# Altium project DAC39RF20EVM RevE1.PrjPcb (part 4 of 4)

## Sheet DUT Power.SchDoc: DAC39RF20 Power Connections
size 431 x 279 mm; Date: Not shown in title block; ApprovedBy: Not shown in title block; CheckedBy: Not shown in title block; Author: Not shown in title block; CompanyName: Not shown in title block; Engineer: Not shown in title block; Organization: Not shown in title block; Address1: Not shown in title block; Address2: Not shown in title block; Address3: Not shown in title block; Address4: Not shown in title block; DocumentNumber: 1; Revision: Use project parameter SCH_Rev; SheetNumber: 16; SheetTotal: 21; PageSetup: Record=PageOptions¦CenterHorizontal=True¦CenterVertical=True¦PrintScale=1.00¦XCorrection=1.00¦YCorrection=1.00¦PrintKind=0¦BorderSize=5000000¦LeftOffset=0¦BottomOffset=0¦Orientation=2¦PaperLength=1000¦PaperWidth=1000¦Scale=100¦PaperSource=15¦PrintQuality=600¦MediaType=1¦DitherType=10¦PaperKind=Letter¦PrintScaleMode=1
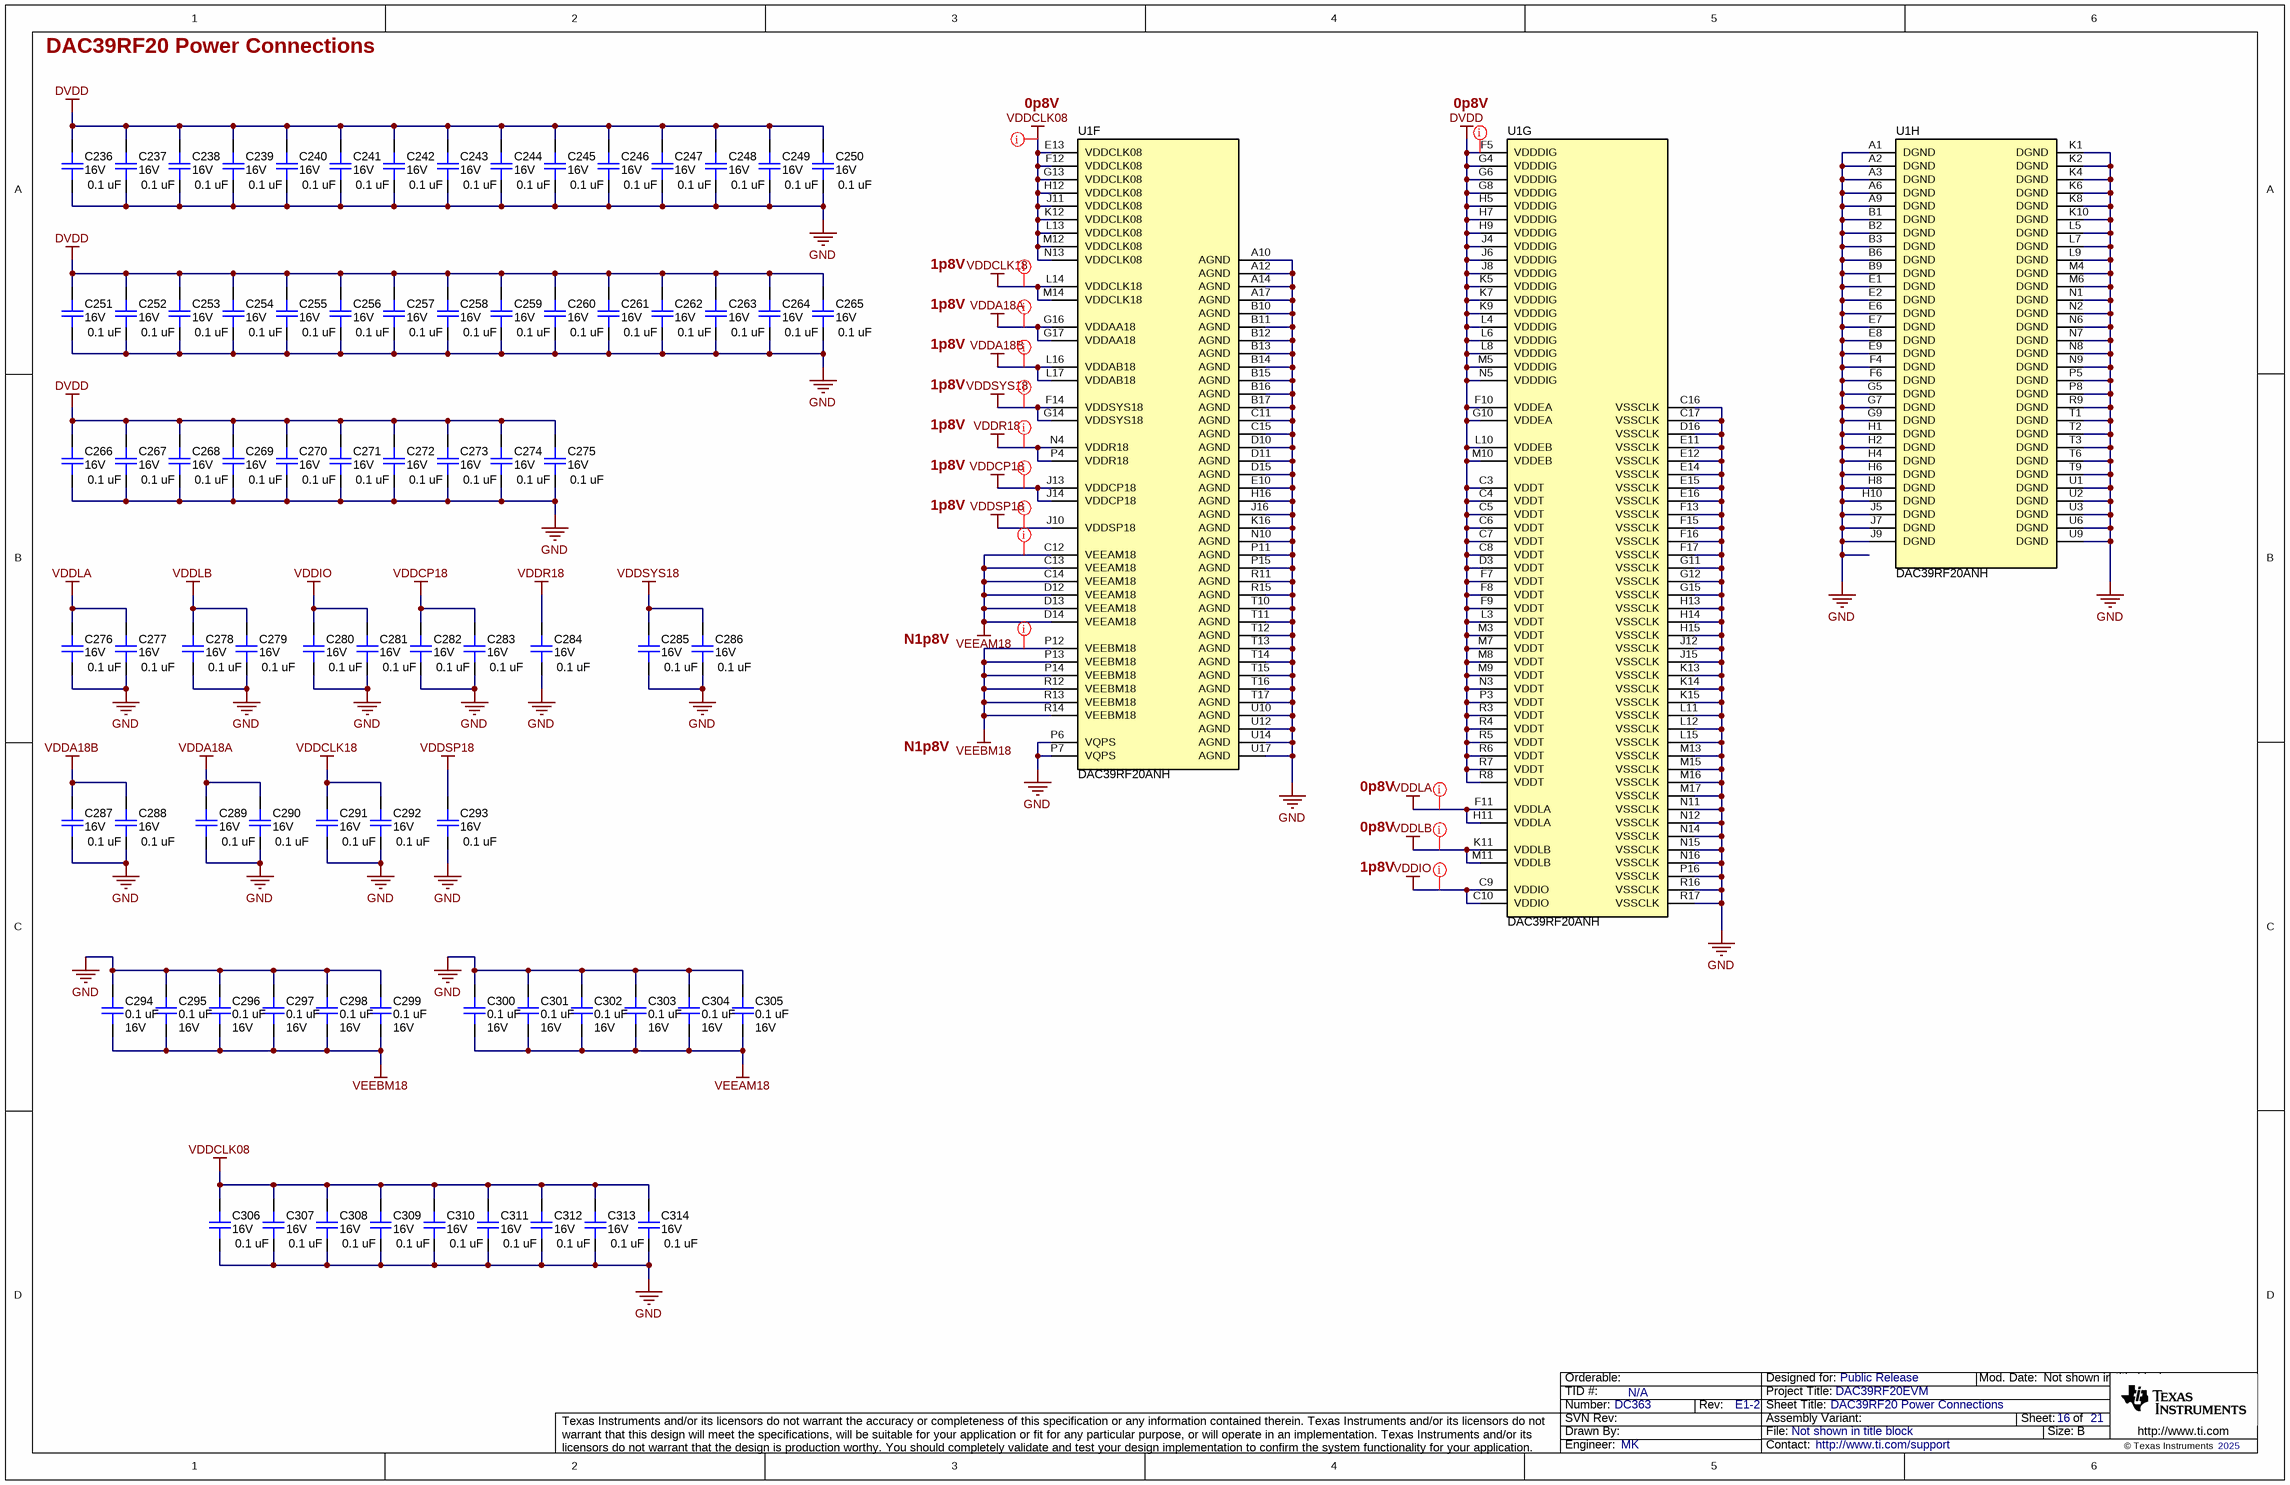
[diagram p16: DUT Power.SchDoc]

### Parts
C236  value 0.1 uF  Voltage - Rated: 16V  [0201_cap]  (hidden comment: GRM033Z71C104KE14D)
C237  value 0.1 uF  Voltage - Rated: 16V  [0201_cap]  (hidden comment: GRM033Z71C104KE14D)
C238  value 0.1 uF  Voltage - Rated: 16V  [0201_cap]  (hidden comment: GRM033Z71C104KE14D)
C239  value 0.1 uF  Voltage - Rated: 16V  [0201_cap]  (hidden comment: GRM033Z71C104KE14D)
C240  value 0.1 uF  Voltage - Rated: 16V  [0201_cap]  (hidden comment: GRM033Z71C104KE14D)
C241  value 0.1 uF  Voltage - Rated: 16V  [0201_cap]  (hidden comment: GRM033Z71C104KE14D)
C242  value 0.1 uF  Voltage - Rated: 16V  [0201_cap]  (hidden comment: GRM033Z71C104KE14D)
C243  value 0.1 uF  Voltage - Rated: 16V  [0201_cap]  (hidden comment: GRM033Z71C104KE14D)
C244  value 0.1 uF  Voltage - Rated: 16V  [0201_cap]  (hidden comment: GRM033Z71C104KE14D)
C245  value 0.1 uF  Voltage - Rated: 16V  [0201_cap]  (hidden comment: GRM033Z71C104KE14D)
C246  value 0.1 uF  Voltage - Rated: 16V  [0201_cap]  (hidden comment: GRM033Z71C104KE14D)
C247  value 0.1 uF  Voltage - Rated: 16V  [0201_cap]  (hidden comment: GRM033Z71C104KE14D)
C248  value 0.1 uF  Voltage - Rated: 16V  [0201_cap]  (hidden comment: GRM033Z71C104KE14D)
C249  value 0.1 uF  Voltage - Rated: 16V  [0201_cap]  (hidden comment: GRM033Z71C104KE14D)
C250  value 0.1 uF  Voltage - Rated: 16V  [0201_cap]  (hidden comment: GRM033Z71C104KE14D)
C251  value 0.1 uF  Voltage - Rated: 16V  [0201_cap]  (hidden comment: GRM033Z71C104KE14D)
C252  value 0.1 uF  Voltage - Rated: 16V  [0201_cap]  (hidden comment: GRM033Z71C104KE14D)
C253  value 0.1 uF  Voltage - Rated: 16V  [0201_cap]  (hidden comment: GRM033Z71C104KE14D)
C254  value 0.1 uF  Voltage - Rated: 16V  [0201_cap]  (hidden comment: GRM033Z71C104KE14D)
C255  value 0.1 uF  Voltage - Rated: 16V  [0201_cap]  (hidden comment: GRM033Z71C104KE14D)
C256  value 0.1 uF  Voltage - Rated: 16V  [0201_cap]  (hidden comment: GRM033Z71C104KE14D)
C257  value 0.1 uF  Voltage - Rated: 16V  [0201_cap]  (hidden comment: GRM033Z71C104KE14D)
C258  value 0.1 uF  Voltage - Rated: 16V  [0201_cap]  (hidden comment: GRM033Z71C104KE14D)
C259  value 0.1 uF  Voltage - Rated: 16V  [0201_cap]  (hidden comment: GRM033Z71C104KE14D)
C260  value 0.1 uF  Voltage - Rated: 16V  [0201_cap]  (hidden comment: GRM033Z71C104KE14D)
C261  value 0.1 uF  Voltage - Rated: 16V  [0201_cap]  (hidden comment: GRM033Z71C104KE14D)
C262  value 0.1 uF  Voltage - Rated: 16V  [0201_cap]  (hidden comment: GRM033Z71C104KE14D)
C263  value 0.1 uF  Voltage - Rated: 16V  [0201_cap]  (hidden comment: GRM033Z71C104KE14D)
C264  value 0.1 uF  Voltage - Rated: 16V  [0201_cap]  (hidden comment: GRM033Z71C104KE14D)
C265  value 0.1 uF  Voltage - Rated: 16V  [0201_cap]  (hidden comment: GRM033Z71C104KE14D)
C266  value 0.1 uF  Voltage - Rated: 16V  [0201_cap]  (hidden comment: GRM033Z71C104KE14D)
C267  value 0.1 uF  Voltage - Rated: 16V  [0201_cap]  (hidden comment: GRM033Z71C104KE14D)
C268  value 0.1 uF  Voltage - Rated: 16V  [0201_cap]  (hidden comment: GRM033Z71C104KE14D)
C269  value 0.1 uF  Voltage - Rated: 16V  [0201_cap]  (hidden comment: GRM033Z71C104KE14D)
C270  value 0.1 uF  Voltage - Rated: 16V  [0201_cap]  (hidden comment: GRM033Z71C104KE14D)
C271  value 0.1 uF  Voltage - Rated: 16V  [0201_cap]  (hidden comment: GRM033Z71C104KE14D)
C272  value 0.1 uF  Voltage - Rated: 16V  [0201_cap]  (hidden comment: GRM033Z71C104KE14D)
C273  value 0.1 uF  Voltage - Rated: 16V  [0201_cap]  (hidden comment: GRM033Z71C104KE14D)
C274  value 0.1 uF  Voltage - Rated: 16V  [0201_cap]  (hidden comment: GRM033Z71C104KE14D)
C275  value 0.1 uF  Voltage - Rated: 16V  [0201_cap]  (hidden comment: GRM033Z71C104KE14D)
C276  value 0.1 uF  Voltage - Rated: 16V  [0201_cap]  (hidden comment: GRM033Z71C104KE14D)
C277  value 0.1 uF  Voltage - Rated: 16V  [0201_cap]  (hidden comment: GRM033Z71C104KE14D)
C278  value 0.1 uF  Voltage - Rated: 16V  [0201_cap]  (hidden comment: GRM033Z71C104KE14D)
C279  value 0.1 uF  Voltage - Rated: 16V  [0201_cap]  (hidden comment: GRM033Z71C104KE14D)
C280  value 0.1 uF  Voltage - Rated: 16V  [0201_cap]  (hidden comment: GRM033Z71C104KE14D)
C281  value 0.1 uF  Voltage - Rated: 16V  [0201_cap]  (hidden comment: GRM033Z71C104KE14D)
C282  value 0.1 uF  Voltage - Rated: 16V  [0201_cap]  (hidden comment: GRM033Z71C104KE14D)
C283  value 0.1 uF  Voltage - Rated: 16V  [0201_cap]  (hidden comment: GRM033Z71C104KE14D)
C284  value 0.1 uF  Voltage - Rated: 16V  [0201_cap]  (hidden comment: GRM033Z71C104KE14D)
C285  value 0.1 uF  Voltage - Rated: 16V  [0201_cap]  (hidden comment: GRM033Z71C104KE14D)
C286  value 0.1 uF  Voltage - Rated: 16V  [0201_cap]  (hidden comment: GRM033Z71C104KE14D)
C287  value 0.1 uF  Voltage - Rated: 16V  [0201_cap]  (hidden comment: GRM033Z71C104KE14D)
C288  value 0.1 uF  Voltage - Rated: 16V  [0201_cap]  (hidden comment: GRM033Z71C104KE14D)
C289  value 0.1 uF  Voltage - Rated: 16V  [0201_cap]  (hidden comment: GRM033Z71C104KE14D)
C290  value 0.1 uF  Voltage - Rated: 16V  [0201_cap]  (hidden comment: GRM033Z71C104KE14D)
C291  value 0.1 uF  Voltage - Rated: 16V  [0201_cap]  (hidden comment: GRM033Z71C104KE14D)
C292  value 0.1 uF  Voltage - Rated: 16V  [0201_cap]  (hidden comment: GRM033Z71C104KE14D)
C293  value 0.1 uF  Voltage - Rated: 16V  [0201_cap]  (hidden comment: GRM033Z71C104KE14D)
C294  value 0.1 uF  Voltage - Rated: 16V  [0201_cap]  (hidden comment: GRM033Z71C104KE14D)
C295  value 0.1 uF  Voltage - Rated: 16V  [0201_cap]  (hidden comment: GRM033Z71C104KE14D)
C296  value 0.1 uF  Voltage - Rated: 16V  [0201_cap]  (hidden comment: GRM033Z71C104KE14D)
C297  value 0.1 uF  Voltage - Rated: 16V  [0201_cap]  (hidden comment: GRM033Z71C104KE14D)
C298  value 0.1 uF  Voltage - Rated: 16V  [0201_cap]  (hidden comment: GRM033Z71C104KE14D)
C299  value 0.1 uF  Voltage - Rated: 16V  [0201_cap]  (hidden comment: GRM033Z71C104KE14D)
C300  value 0.1 uF  Voltage - Rated: 16V  [0201_cap]  (hidden comment: GRM033Z71C104KE14D)
C301  value 0.1 uF  Voltage - Rated: 16V  [0201_cap]  (hidden comment: GRM033Z71C104KE14D)
C302  value 0.1 uF  Voltage - Rated: 16V  [0201_cap]  (hidden comment: GRM033Z71C104KE14D)
C303  value 0.1 uF  Voltage - Rated: 16V  [0201_cap]  (hidden comment: GRM033Z71C104KE14D)
C304  value 0.1 uF  Voltage - Rated: 16V  [0201_cap]  (hidden comment: GRM033Z71C104KE14D)
C305  value 0.1 uF  Voltage - Rated: 16V  [0201_cap]  (hidden comment: GRM033Z71C104KE14D)
C306  value 0.1 uF  Voltage - Rated: 16V  [0201_cap]  (hidden comment: GRM033Z71C104KE14D)
C307  value 0.1 uF  Voltage - Rated: 16V  [0201_cap]  (hidden comment: GRM033Z71C104KE14D)
C308  value 0.1 uF  Voltage - Rated: 16V  [0201_cap]  (hidden comment: GRM033Z71C104KE14D)
C309  value 0.1 uF  Voltage - Rated: 16V  [0201_cap]  (hidden comment: GRM033Z71C104KE14D)
C310  value 0.1 uF  Voltage - Rated: 16V  [0201_cap]  (hidden comment: GRM033Z71C104KE14D)
C311  value 0.1 uF  Voltage - Rated: 16V  [0201_cap]  (hidden comment: GRM033Z71C104KE14D)
C312  value 0.1 uF  Voltage - Rated: 16V  [0201_cap]  (hidden comment: GRM033Z71C104KE14D)
C313  value 0.1 uF  Voltage - Rated: 16V  [0201_cap]  (hidden comment: GRM033Z71C104KE14D)
C314  value 0.1 uF  Voltage - Rated: 16V  [0201_cap]  (hidden comment: GRM033Z71C104KE14D)
U1  DAC39RF20ANH  [ANH0289A]  (parts F,G,H of 8)

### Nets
DVDD: C236.1 C237.1 C238.1 C239.1 C240.1 C241.1 C242.1 C243.1 C244.1 C245.1 C246.1 C247.1 C248.1 C249.1 C250.1 C251.1 C252.1 C253.1 C254.1 C255.1 C256.1 C257.1 C258.1 C259.1 C260.1 C261.1 C262.1 C263.1 C264.1 C265.1 C266.1 C267.1 C268.1 C269.1 C270.1 C271.1 C272.1 C273.1 C274.1 C275.1 U1.C3(VDDT) U1.C4(VDDT) U1.C5(VDDT) U1.C6(VDDT) U1.C7(VDDT) U1.C8(VDDT) U1.D3(VDDT) U1.F5(VDDDIG) U1.F7(VDDT) U1.F8(VDDT) U1.F9(VDDT) U1.F10(VDDEA) U1.G4(VDDDIG) U1.G6(VDDDIG) U1.G8(VDDDIG) U1.G10(VDDEA) U1.H5(VDDDIG) U1.H7(VDDDIG) U1.H9(VDDDIG) U1.J4(VDDDIG) U1.J6(VDDDIG) U1.J8(VDDDIG) U1.K5(VDDDIG) U1.K7(VDDDIG) U1.K9(VDDDIG) U1.L3(VDDT) U1.L4(VDDDIG) U1.L6(VDDDIG) U1.L8(VDDDIG) U1.L10(VDDEB) U1.M3(VDDT) U1.M5(VDDDIG) U1.M7(VDDT) U1.M8(VDDT) U1.M9(VDDT) U1.M10(VDDEB) U1.N3(VDDT) U1.N5(VDDDIG) U1.P3(VDDT) U1.R3(VDDT) U1.R4(VDDT) U1.R5(VDDT) U1.R6(VDDT) U1.R7(VDDT) U1.R8(VDDT)
GND: C236.2 C237.2 C238.2 C239.2 C240.2 C241.2 C242.2 C243.2 C244.2 C245.2 C246.2 C247.2 C248.2 C249.2 C250.2 C251.2 C252.2 C253.2 C254.2 C255.2 C256.2 C257.2 C258.2 C259.2 C260.2 C261.2 C262.2 C263.2 C264.2 C265.2 C266.2 C267.2 C268.2 C269.2 C270.2 C271.2 C272.2 C273.2 C274.2 C275.2 C276.2 C277.2 C278.2 C279.2 C280.2 C281.2 C282.2 C283.2 C284.2 C285.2 C286.2 C287.2 C288.2 C289.2 C290.2 C291.2 C292.2 C293.2 C294.2 C295.2 C296.2 C297.2 C298.2 C299.2 C300.2 C301.2 C302.2 C303.2 C304.2 C305.2 C306.2 C307.2 C308.2 C309.2 C310.2 C311.2 C312.2 C313.2 C314.2 U1.A1(DGND) U1.A2(DGND) U1.A3(DGND) U1.A6(DGND) U1.A9(DGND) U1.A10(AGND) U1.A12(AGND) U1.A14(AGND) U1.A17(AGND) U1.B1(DGND) U1.B2(DGND) U1.B3(DGND) U1.B6(DGND) U1.B9(DGND) U1.B10(AGND) U1.B11(AGND) U1.B12(AGND) U1.B13(AGND) U1.B14(AGND) U1.B15(AGND) U1.B16(AGND) U1.B17(AGND) U1.C11(AGND) U1.C15(AGND) U1.C16(VSSCLK) U1.C17(VSSCLK) U1.D10(AGND) U1.D11(AGND) U1.D15(AGND) U1.D16(VSSCLK) U1.E1(DGND) U1.E2(DGND) U1.E6(DGND) U1.E7(DGND) U1.E8(DGND) U1.E9(DGND) U1.E10(AGND) U1.E11(VSSCLK) U1.E12(VSSCLK) U1.E14(VSSCLK) U1.E15(VSSCLK) U1.E16(VSSCLK) U1.F4(DGND) U1.F6(DGND) U1.F13(VSSCLK) U1.F15(VSSCLK) U1.F16(VSSCLK) U1.F17(VSSCLK) U1.G5(DGND) U1.G7(DGND) U1.G9(DGND) U1.G11(VSSCLK) U1.G12(VSSCLK) U1.G15(VSSCLK) U1.H1(DGND) U1.H2(DGND) U1.H4(DGND) U1.H6(DGND) U1.H8(DGND) U1.H10(DGND) U1.H13(VSSCLK) U1.H14(VSSCLK) U1.H15(VSSCLK) U1.H16(AGND) U1.J5(DGND) U1.J7(DGND) U1.J9(DGND) U1.J12(VSSCLK) U1.J15(VSSCLK) U1.J16(AGND) U1.K1(DGND) U1.K2(DGND) U1.K4(DGND) U1.K6(DGND) U1.K8(DGND) U1.K10(DGND) U1.K13(VSSCLK) U1.K14(VSSCLK) U1.K15(VSSCLK) U1.K16(AGND) U1.L5(DGND) U1.L7(DGND) U1.L9(DGND) U1.L11(VSSCLK) U1.L12(VSSCLK) U1.L15(VSSCLK) U1.M4(DGND) U1.M6(DGND) U1.M13(VSSCLK) U1.M15(VSSCLK) U1.M16(VSSCLK) U1.M17(VSSCLK) U1.N1(DGND) U1.N2(DGND) U1.N6(DGND) U1.N7(DGND) U1.N8(DGND) U1.N9(DGND) U1.N10(AGND) U1.N11(VSSCLK) U1.N12(VSSCLK) U1.N14(VSSCLK) U1.N15(VSSCLK) U1.N16(VSSCLK) U1.P5(DGND) U1.P6(VQPS) U1.P7(VQPS) U1.P8(DGND) U1.P11(AGND) U1.P15(AGND) U1.P16(VSSCLK) U1.R9(DGND) U1.R11(AGND) U1.R15(AGND) U1.R16(VSSCLK) U1.R17(VSSCLK) U1.T1(DGND) U1.T2(DGND) U1.T3(DGND) U1.T6(DGND) U1.T9(DGND) U1.T10(AGND) U1.T11(AGND) U1.T12(AGND) U1.T13(AGND) U1.T14(AGND) U1.T15(AGND) U1.T16(AGND) U1.T17(AGND) U1.U1(DGND) U1.U2(DGND) U1.U3(DGND) U1.U6(DGND) U1.U9(DGND) U1.U10(AGND) U1.U12(AGND) U1.U14(AGND) U1.U17(AGND)
VDDA18A: C289.1 C290.1 U1.G16(VDDAA18) U1.G17(VDDAA18)
VDDA18B: C287.1 C288.1 U1.L16(VDDAB18) U1.L17(VDDAB18)
VDDCLK08: C306.1 C307.1 C308.1 C309.1 C310.1 C311.1 C312.1 C313.1 C314.1 U1.E13(VDDCLK08) U1.F12(VDDCLK08) U1.G13(VDDCLK08) U1.H12(VDDCLK08) U1.J11(VDDCLK08) U1.K12(VDDCLK08) U1.L13(VDDCLK08) U1.M12(VDDCLK08) U1.N13(VDDCLK08)
VDDCLK18: C291.1 C292.1 U1.L14(VDDCLK18) U1.M14(VDDCLK18)
VDDCP18: C282.1 C283.1 U1.J13(VDDCP18) U1.J14(VDDCP18)
VDDIO: C280.1 C281.1 U1.C9(VDDIO) U1.C10(VDDIO)
VDDLA: C276.1 C277.1 U1.F11(VDDLA) U1.H11(VDDLA)
VDDLB: C278.1 C279.1 U1.K11(VDDLB) U1.M11(VDDLB)
VDDR18: C284.1 U1.N4(VDDR18) U1.P4(VDDR18)
VDDSP18: C293.1 U1.J10(VDDSP18)
VDDSYS18: C285.1 C286.1 U1.F14(VDDSYS18) U1.G14(VDDSYS18)
VEEAM18: C300.1 C301.1 C302.1 C303.1 C304.1 C305.1 U1.C12(VEEAM18) U1.C13(VEEAM18) U1.C14(VEEAM18) U1.D12(VEEAM18) U1.D13(VEEAM18) U1.D14(VEEAM18)
VEEBM18: C294.1 C295.1 C296.1 C297.1 C298.1 C299.1 U1.P12(VEEBM18) U1.P13(VEEBM18) U1.P14(VEEBM18) U1.R12(VEEBM18) U1.R13(VEEBM18) U1.R14(VEEBM18)

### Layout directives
net class Power; net class PWR1: DVDD
net class Power; net class PWR2: VDDCLK08, VDDLA, VDDLB
net class Power; net class PWR4: VDDCLK18, VDDIO, VDDR18, VDDSP18, VDDSYS18
net class Power; net class PWR3: VDDA18A, VDDA18B, VDDCP18, VEEAM18, VEEBM18

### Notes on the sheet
- (near U1) 0p8V
- 1p8V
- N1p8V
- 0p8V

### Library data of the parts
C236-C314 = capcc09263: CAP CER 0.1UF 16V X7R 0201; Manufacturer: Murata Electronics; SizeZ_mm: 0.33; SizeX_mm: 0.6; SizeY_mm: 0.3; CompType: Capacitor Ceramic; Tolerance: ±10%
U1 = cmp00515: Manufacturer: Texas Instruments; CompType: DAC

## Sheet FMC+ Sections A-E.SchDoc: FMC+ Section Rows A - E
size 431 x 279 mm; Date: Not shown in title block; ApprovedBy: Not shown in title block; CheckedBy: Not shown in title block; Author: Not shown in title block; CompanyName: Not shown in title block; Engineer: Not shown in title block; Organization: Not shown in title block; Address1: Not shown in title block; Address2: Not shown in title block; Address3: Not shown in title block; Address4: Not shown in title block; DocumentNumber: 2; Revision: Use project parameter SCH_Rev; SheetNumber: 17; SheetTotal: 21; PageSetup: Record=PageOptions¦CenterHorizontal=True¦CenterVertical=True¦PrintScale=1.00¦XCorrection=1.00¦YCorrection=1.00¦PrintKind=0¦BorderSize=5000000¦LeftOffset=0¦BottomOffset=0¦Orientation=2¦PaperLength=1000¦PaperWidth=1000¦Scale=100¦PaperSource=15¦PrintQuality=600¦MediaType=1¦DitherType=10¦PaperKind=Letter¦PrintScaleMode=1
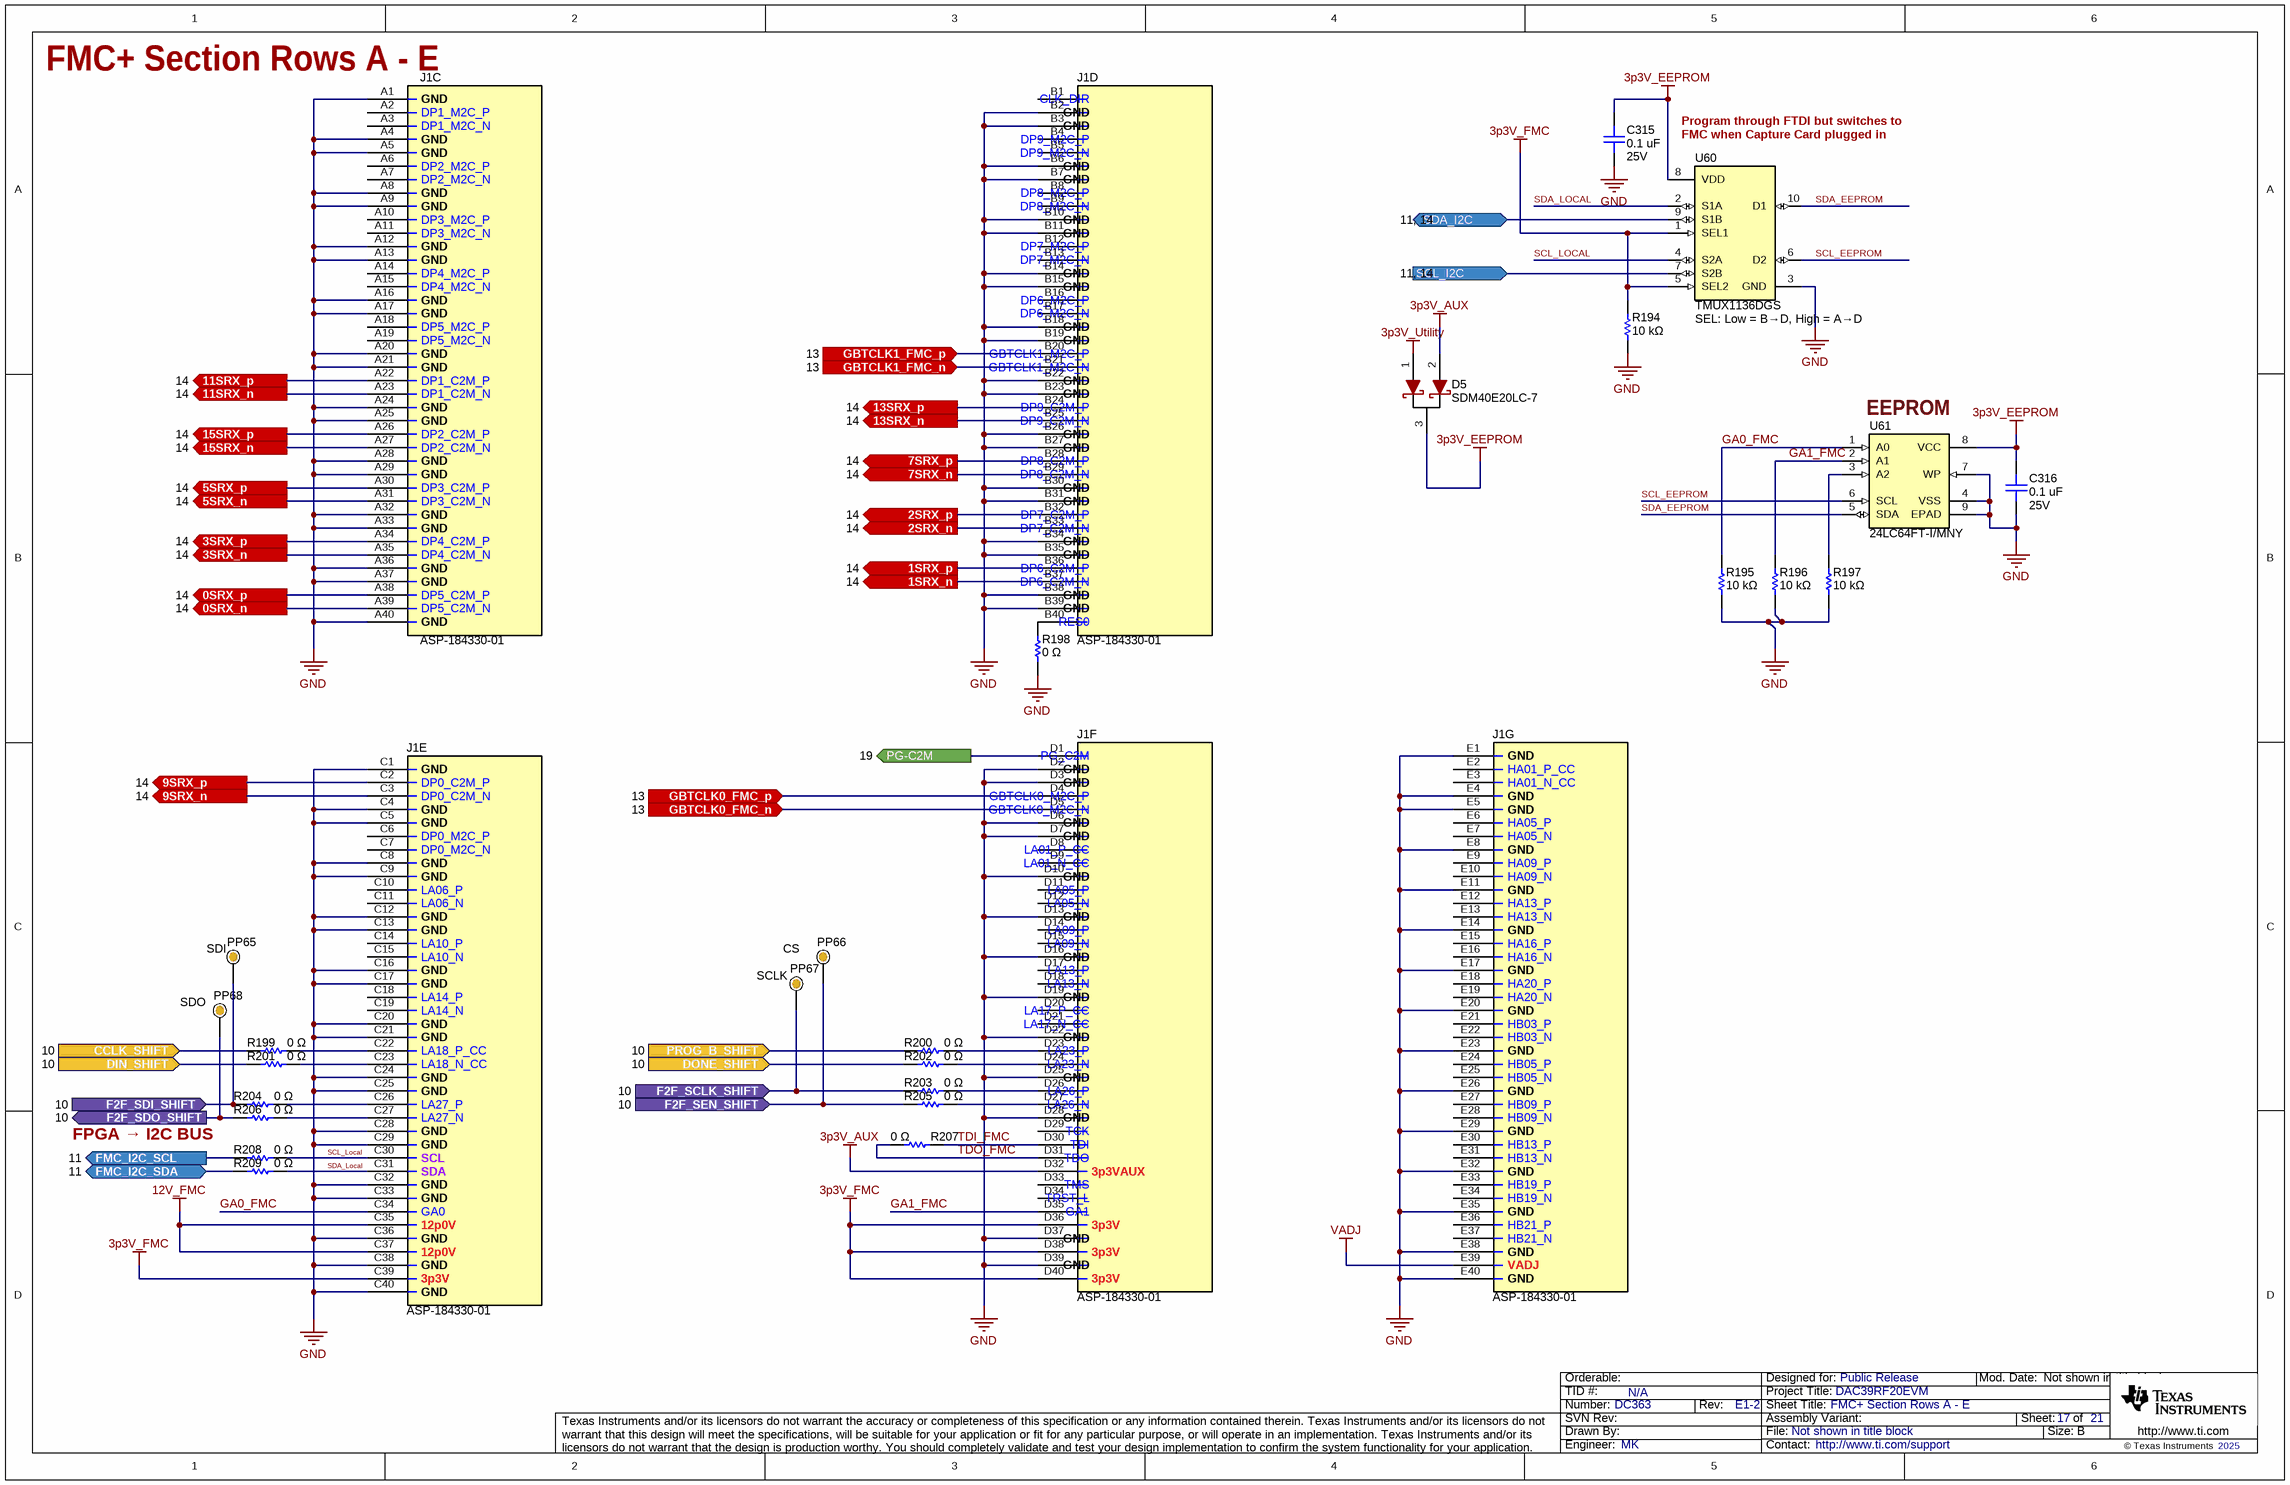
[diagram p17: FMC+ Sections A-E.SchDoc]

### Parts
C315  value 0.1 uF  Voltage - Rated: 25V  [0402L_cap]  (hidden comment: GRT155R71E104KE01J)
C316  value 0.1 uF  Voltage - Rated: 25V  [0402L_cap]  (hidden comment: GRT155R71E104KE01J)
D5  SDM40E20LC-7  [SOT-323-DIO]
J1  ASP-184330-01  [Samtec_ASP-184330-01]  (parts C,D,E,F,G of 14)
PP65  Text1: SDI  [ProbePoint_TH_40mil]  (hidden comment: Probe Point)  (no BOM)
PP66  Text1: CS  [ProbePoint_TH_40mil]  (hidden comment: Probe Point)  (no BOM)
PP67  Text1: SCLK  [ProbePoint_TH_40mil]  (hidden comment: Probe Point)  (no BOM)
PP68  Text1: SDO  [ProbePoint_TH_40mil]  (hidden comment: Probe Point)  (no BOM)
R194  value 10 kΩ  [0402L]  (hidden comment: ERJ-2RKF1002X)
R195  value 10 kΩ  [0201]  (hidden comment: ERJ-1GNJ103C)
R196  value 10 kΩ  [0201]  (hidden comment: ERJ-1GNJ103C)
R197  value 10 kΩ  [0201]  (hidden comment: ERJ-1GNJ103C)
R198  value 0 Ω  [0201]  (hidden comment: ERJ-1GN0R00C)
R199  value 0 Ω  [0201]  (hidden comment: ERJ-1GN0R00C)
R200  value 0 Ω  [0201]  (hidden comment: ERJ-1GN0R00C)
R201  value 0 Ω  [0201]  (hidden comment: ERJ-1GN0R00C)
R202  value 0 Ω  [0201]  (hidden comment: ERJ-1GN0R00C)
R203  value 0 Ω  [0201]  (hidden comment: ERJ-1GN0R00C)
R204  value 0 Ω  [0201]  (hidden comment: ERJ-1GN0R00C)
R205  value 0 Ω  [0201]  (hidden comment: ERJ-1GN0R00C)
R206  value 0 Ω  [0201]  (hidden comment: ERJ-1GN0R00C)
R207  value 0 Ω  [0201]  (hidden comment: ERJ-1GN0R00C)
R208  value 0 Ω  [0201]  (hidden comment: ERJ-1GN0R00C)
R209  value 0 Ω  [0201]  (hidden comment: ERJ-1GN0R00C)
U60  TMUX1136DGS  Text1: SEL: Low = B→D, High = A→D  [DQA0010A]
U61  24LC64FT-I/MNY  [TDFN8]

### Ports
0SRX_n (out, see 14), 0SRX_p (out, see 14), 1SRX_n (out, see 14), 1SRX_p (out, see 14), 2SRX_n (out, see 14), 2SRX_p (out, see 14), 3SRX_n (out, see 14), 3SRX_p (out, see 14), 5SRX_n (out, see 14), 5SRX_p (out, see 14), 7SRX_n (out, see 14), 7SRX_p (out, see 14), 9SRX_n (out, see 14), 9SRX_p (out, see 14), 11SRX_n (out, see 14), 11SRX_p (out, see 14), 13SRX_n (out, see 14), 13SRX_p (out, see 14), 15SRX_n (out, see 14), 15SRX_p (out, see 14), CCLK_SHIFT (in, see 10), DIN_SHIFT (in, see 10), DONE_SHIFT (in, see 10), F2F_SCLK_SHIFT (in, see 10), F2F_SDI_SHIFT (in, see 10), F2F_SDO_SHIFT (out, see 10), F2F_SEN_SHIFT (in, see 10), FMC_I2C_SCL (out, see 11), FMC_I2C_SDA (bidir, see 11), GBTCLK0_FMC_n (in, see 13), GBTCLK0_FMC_p (in, see 13), GBTCLK1_FMC_n (in, see 13), GBTCLK1_FMC_p (in, see 13), PG-C2M (out, see 19), PROG_B_SHIFT (in, see 10), SCL_I2C (in, see 11, 14), SDA_I2C (bidir, see 11, 14)

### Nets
3p3V_AUX: D5.2(A) J1.D32
3p3V_EEPROM: C315.2 C316.2 D5.3(A) U60.8(VDD) U61.8(VCC)
3p3V_FMC: J1.C39 J1.D36 J1.D38 J1.D40 R194.2 U60.1(SEL1) U60.5(SEL2)
3p3V_Utility: D5.1(K)
12V_FMC: J1.C35 J1.C37
GND: C315.1 C316.1 J1.A1 J1.A4 J1.A5 J1.A8 J1.A9 J1.A12 J1.A13 J1.A16 J1.A17 J1.A20 J1.A21 J1.A24 J1.A25 J1.A28 J1.A29 J1.A32 J1.A33 J1.A36 J1.A37 J1.A40 J1.B2 J1.B3 J1.B6 J1.B7 J1.B10 J1.B11 J1.B14 J1.B15 J1.B18 J1.B19 J1.B22 J1.B23 J1.B26 J1.B27 J1.B30 J1.B31 J1.B34 J1.B35 J1.B38 J1.B39 J1.C1 J1.C4 J1.C5 J1.C8 J1.C9 J1.C12 J1.C13 J1.C16 J1.C17 J1.C20 J1.C21 J1.C24 J1.C25 J1.C28 J1.C29 J1.C32 J1.C33 J1.C36 J1.C38 J1.C40 J1.D2 J1.D3 J1.D6 J1.D7 J1.D10 J1.D13 J1.D16 J1.D19 J1.D22 J1.D25 J1.D28 J1.D37 J1.D39 J1.E1 J1.E4 J1.E5 J1.E8 J1.E11 J1.E14 J1.E17 J1.E20 J1.E23 J1.E26 J1.E29 J1.E32 J1.E35 J1.E38 J1.E40 R194.1 R195.1 R196.1 R197.1 R198.1 U60.3(GND) U61.4(VSS) U61.7(WP) U61.9(EPAD)
VADJ: J1.E39
0SRX_n: J1.A39 ; port 0SRX_n
0SRX_p: J1.A38 ; port 0SRX_p
1SRX_n: J1.B37 ; port 1SRX_n
1SRX_p: J1.B36 ; port 1SRX_p
2SRX_n: J1.B33 ; port 2SRX_n
2SRX_p: J1.B32 ; port 2SRX_p
3SRX_n: J1.A35 ; port 3SRX_n
3SRX_p: J1.A34 ; port 3SRX_p
5SRX_n: J1.A31 ; port 5SRX_n
5SRX_p: J1.A30 ; port 5SRX_p
7SRX_n: J1.B29 ; port 7SRX_n
7SRX_p: J1.B28 ; port 7SRX_p
9SRX_n: J1.C3 ; port 9SRX_n
9SRX_p: J1.C2 ; port 9SRX_p
11SRX_n: J1.A23 ; port 11SRX_n
11SRX_p: J1.A22 ; port 11SRX_p
13SRX_n: J1.B25 ; port 13SRX_n
13SRX_p: J1.B24 ; port 13SRX_p
15SRX_n: J1.A27 ; port 15SRX_n
15SRX_p: J1.A26 ; port 15SRX_p
CCLK_SHIFT: R199.1 ; port CCLK_SHIFT
DIN_SHIFT: R201.1 ; port DIN_SHIFT
DONE_SHIFT: R202.1 ; port DONE_SHIFT
F2F_SCLK_SHIFT: PP67.1 R203.1 ; port F2F_SCLK_SHIFT
F2F_SDI_SHIFT: PP65.1 R204.1 ; port F2F_SDI_SHIFT
F2F_SDO_SHIFT: PP68.1 R206.1 ; port F2F_SDO_SHIFT
F2F_SEN_SHIFT: PP66.1 R205.1 ; port F2F_SEN_SHIFT
FMC_I2C_SCL: R208.1 ; port FMC_I2C_SCL
FMC_I2C_SDA: R209.1 ; port FMC_I2C_SDA
GA0_FMC: J1.C34 R195.2 U61.1(A0)
GA1_FMC: J1.D35 R196.2 U61.2(A1)
GBTCLK0_FMC_n: J1.D5 ; port GBTCLK0_FMC_n
GBTCLK0_FMC_p: J1.D4 ; port GBTCLK0_FMC_p
GBTCLK1_FMC_n: J1.B21 ; port GBTCLK1_FMC_n
GBTCLK1_FMC_p: J1.B20 ; port GBTCLK1_FMC_p
PG-C2M: J1.D1 ; port PG-C2M
PROG_B_SHIFT: R200.1 ; port PROG_B_SHIFT
SCL_EEPROM: U60.6(D2) U61.6(SCL)
SCL_I2C: U60.7(S2B) ; port SCL_I2C
SCL_Local: J1.C30 R208.2 U60.4(S2A)
SDA_EEPROM: U60.10(D1) U61.5(SDA)
SDA_I2C: U60.9(S1B) ; port SDA_I2C
SDA_Local: J1.C31 R209.2 U60.2(S1A)
TDI_FMC: J1.D30 R207.2
TDO_FMC: J1.D31 R207.1
NetJ1_B40: J1.B40 R198.2
NetJ1_C22: J1.C22 R199.2
NetJ1_C23: J1.C23 R201.2
NetJ1_C26: J1.C26 R204.2
NetJ1_C27: J1.C27 R206.2
NetJ1_D23: J1.D23 R200.2
NetJ1_D24: J1.D24 R202.2
NetJ1_D26: J1.D26 R203.2
NetJ1_D27: J1.D27 R205.2
NetR197_2: R197.2 U61.3(A2)

Not connected (* = marked no-connect by the designer): J1 A2 A3 A6 A7 A10 A11 A14 A15 A18 A19 B1 B4 B5 B8 B9 B12 B13 B16 B17 C6 C7 C10 C11 C14 C15 C18 C19 D8 D9 D11 D12 D14 D15 D17 D18 D20 D21 D29 D33 D34 E2 E3 E6 E7 E9 E10 E12 E13 E15 E16 E18 E19 E21 E22 E24 E25 E27 E28 E30 E31 E33 E34 E36 E37

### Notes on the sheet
- (near U60) Program through FTDI but switches to FMC when Capture Card plugged in
- (near U61) EEPROM
- FPGA → I2C BUS

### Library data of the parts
C315 C316 = capcc09401: CAP CER 0.1UF 25V X7R 0402; Manufacturer: Murata; CompType: Capacitor Ceramic; Tolerance: ±10%; SizeX_mm: 1; SizeY_mm: 0.5; SizeZ_mm: 0.7
D5 = SDM40E20LC-7: Diode Array 1 Pair Common Cathode 20 V 400mA (DC); Manufacturer: Diodes Inc; Text1: 310mV@100mA
J1 = ASP-184330-01: FMC+, High Density Array, Male / EVM Connector 40x14; Manufacturer: Samtec; UniqueID: cmp00011; Pitch (mm): 1.27
PP65-PP68 = Probe Point: Probe Point that can be used in lue of a test point; UniqueID: cmp00025
R194 = RSMD040200314: RES SMD 10K OHM 1% 1/10W 0402; Manufacturer: Panasonic Electronic Components; CompType: Resistor SMD; Power (Watts): 0.1W, 1/10W; Temperature Coefficient: ±100ppm/°C; SizeX_mm: 1; SizeY_mm: 0.5; SizeZ_mm: 0.4
R195-R197 = RSMD020101186: RES SMD 10K OHM 5% 1/20W 0201; Manufacturer: Panasonic Electronic Components; CompType: Resistor SMD; Power (Watts): 0.05W, 1/20W; Temperature Coefficient: ±200ppm/°C
R198-R209 = RSMD020101699: RES SMD 0 OHM JUMPER 1/20W 0201; Manufacturer: Panasonic Electronic Components; CompType: Resistor SMD; Power (Watts): 0.05W, 1/20W
U60 = cmp00307: 5-V low-leakage-current, 2: 1, 2-channel precision analog switch; PartNumber: TMUX1136DQA; Manufacturer: Texas Instruments; CompType: MUX
U61 = cmp00154: EEPROM 64K 8KX8 1.8V SER EE IND 1/4AWP RPO; Manufacturer: Microchip

## Sheet FMC+ Sections F-H, J, K.SchDoc: FMC+ Section Rows F - H, J, K
size 431 x 279 mm; Date: Not shown in title block; ApprovedBy: Not shown in title block; CheckedBy: Not shown in title block; Author: Not shown in title block; CompanyName: Not shown in title block; Engineer: Not shown in title block; Organization: Not shown in title block; Address1: Not shown in title block; Address2: Not shown in title block; Address3: Not shown in title block; Address4: Not shown in title block; DocumentNumber: 3; Revision: Use project parameter SCH_Rev; SheetNumber: 18; SheetTotal: 21; PageSetup: Record=PageOptions¦CenterHorizontal=True¦CenterVertical=True¦PrintScale=1.00¦XCorrection=1.00¦YCorrection=1.00¦PrintKind=0¦BorderSize=5000000¦LeftOffset=0¦BottomOffset=0¦Orientation=2¦PaperLength=1000¦PaperWidth=1000¦Scale=100¦PaperSource=15¦PrintQuality=600¦MediaType=1¦DitherType=10¦PaperKind=Letter¦PrintScaleMode=1
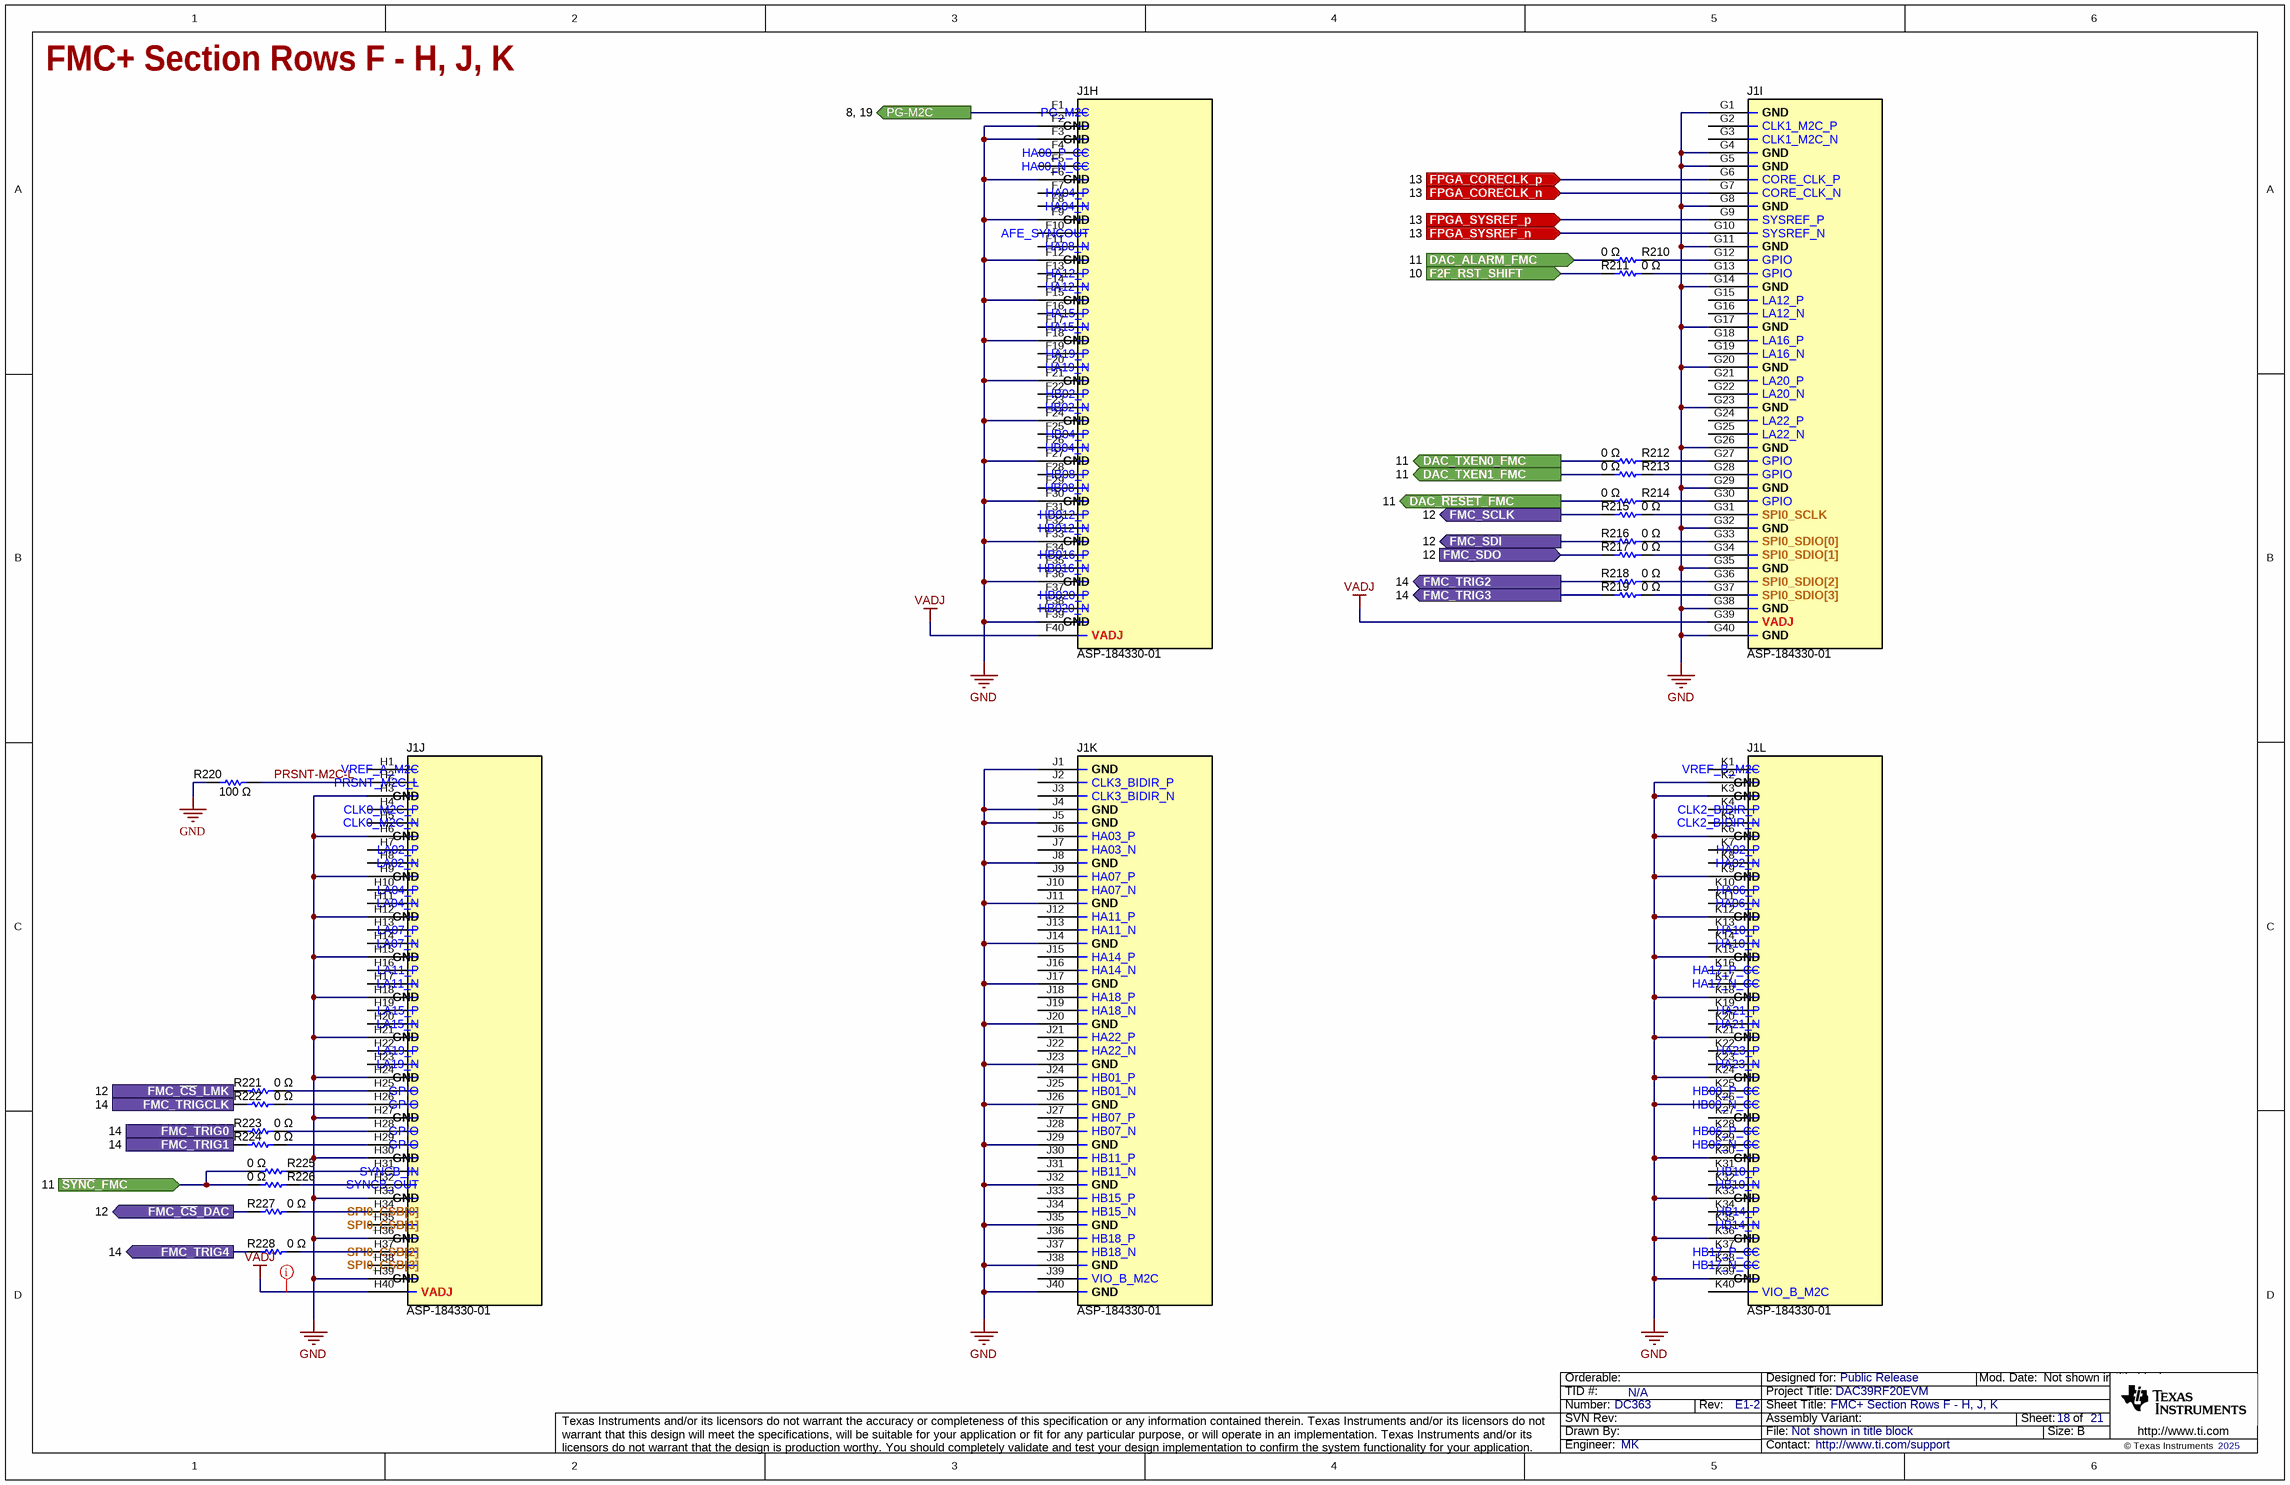
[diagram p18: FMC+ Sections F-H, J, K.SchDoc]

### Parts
J1  ASP-184330-01  [Samtec_ASP-184330-01]  (parts H,I,J,K,L of 14)
R210  value 0 Ω  [0201]  (hidden comment: ERJ-1GN0R00C)
R211  value 0 Ω  [0201]  (hidden comment: ERJ-1GN0R00C)
R212  value 0 Ω  [0201]  (hidden comment: ERJ-1GN0R00C)
R213  value 0 Ω  [0201]  (hidden comment: ERJ-1GN0R00C)
R214  value 0 Ω  [0201]  (hidden comment: ERJ-1GN0R00C)
R215  value 0 Ω  [0201]  (hidden comment: ERJ-1GN0R00C)
R216  value 0 Ω  [0201]  (hidden comment: ERJ-1GN0R00C)
R217  value 0 Ω  [0201]  (hidden comment: ERJ-1GN0R00C)
R218  value 0 Ω  [0201]  (hidden comment: ERJ-1GN0R00C)
R219  value 0 Ω  [0201]  (hidden comment: ERJ-1GN0R00C)
R220  value 100 Ω  [0402L]  (hidden comment: ERJ-2RKF1000X)
R221  value 0 Ω  [0201]  (hidden comment: ERJ-1GN0R00C)
R222  value 0 Ω  [0201]  (hidden comment: ERJ-1GN0R00C)
R223  value 0 Ω  [0201]  (hidden comment: ERJ-1GN0R00C)
R224  value 0 Ω  [0201]  (hidden comment: ERJ-1GN0R00C)
R225  value 0 Ω  [0201]  (hidden comment: ERJ-1GN0R00C)
R226  value 0 Ω  [0201]  (hidden comment: ERJ-1GN0R00C)
R227  value 0 Ω  [0201]  (hidden comment: ERJ-1GN0R00C)
R228  value 0 Ω  [0201]  (hidden comment: ERJ-1GN0R00C)

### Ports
DAC_ALARM_FMC (in, see 11), DAC_TXEN0_FMC (out, see 11), DAC_TXEN1_FMC (out, see 11), DAC_~{RESET}_FMC (out, see 11), F2F_RST_SHIFT (in, see 10), FMC_SCLK (out, see 12), FMC_SDI (out, see 12), FMC_SDO (in, see 12), FMC_TRIG0 (out, see 14), FMC_TRIG1 (out, see 14), FMC_TRIG2 (out, see 14), FMC_TRIG3 (out, see 14), FMC_TRIG4 (out, see 14), FMC_TRIGCLK (out, see 14), FMC_~{CS}_DAC (out, see 12), FMC_~{CS}_LMK (out, see 12), FPGA_CORECLK_n (in, see 13), FPGA_CORECLK_p (in, see 13), FPGA_SYSREF_n (in, see 13), FPGA_SYSREF_p (in, see 13), PG-M2C (out, see 8, 19), ~{SYNC}_FMC (in, see 11)

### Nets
GND: J1.F2 J1.F3 J1.F6 J1.F9 J1.F12 J1.F15 J1.F18 J1.F21 J1.F24 J1.F27 J1.F30 J1.F33 J1.F36 J1.F39 J1.G1 J1.G4 J1.G5 J1.G8 J1.G11 J1.G14 J1.G17 J1.G20 J1.G23 J1.G26 J1.G29 J1.G32 J1.G35 J1.G38 J1.G40 J1.H3 J1.H6 J1.H9 J1.H12 J1.H15 J1.H18 J1.H21 J1.H24 J1.H27 J1.H30 J1.H33 J1.H36 J1.H39 J1.J1 J1.J4 J1.J5 J1.J8 J1.J11 J1.J14 J1.J17 J1.J20 J1.J23 J1.J26 J1.J29 J1.J32 J1.J35 J1.J38 J1.J40 J1.K2 J1.K3 J1.K6 J1.K9 J1.K12 J1.K15 J1.K18 J1.K21 J1.K24 J1.K26 J1.K30 J1.K33 J1.K36 J1.K39 R220.1
VADJ: J1.F40 J1.G39 J1.H40
DAC_ALARM_FMC: R210.1 ; port DAC_ALARM_FMC
DAC_~{RESET}_FMC: R214.1 ; port DAC_~{RESET}_FMC
DAC_TXEN0_FMC: R212.1 ; port DAC_TXEN0_FMC
DAC_TXEN1_FMC: R213.1 ; port DAC_TXEN1_FMC
F2F_RST_SHIFT: R211.1 ; port F2F_RST_SHIFT
FMC_~{CS}_DAC: R227.1 ; port FMC_~{CS}_DAC
FMC_~{CS}_LMK: R221.1 ; port FMC_~{CS}_LMK
FMC_SCLK: R215.1 ; port FMC_SCLK
FMC_SDI: R216.1 ; port FMC_SDI
FMC_SDO: R217.1 ; port FMC_SDO
FMC_TRIG0: R223.1 ; port FMC_TRIG0
FMC_TRIG1: R224.1 ; port FMC_TRIG1
FMC_TRIG2: R218.1 ; port FMC_TRIG2
FMC_TRIG3: R219.1 ; port FMC_TRIG3
FMC_TRIG4: R228.1 ; port FMC_TRIG4
FMC_TRIGCLK: R222.1 ; port FMC_TRIGCLK
FPGA_CORECLK_n: J1.G7 ; port FPGA_CORECLK_n
FPGA_CORECLK_p: J1.G6 ; port FPGA_CORECLK_p
FPGA_SYSREF_n: J1.G10 ; port FPGA_SYSREF_n
FPGA_SYSREF_p: J1.G9 ; port FPGA_SYSREF_p
PG-M2C: J1.F1 ; port PG-M2C
PRSNT-M2C-L: J1.H2 R220.2
~{SYNC}_FMC: R225.1 R226.1 ; port ~{SYNC}_FMC
NetJ1_G12: J1.G12 R210.2
NetJ1_G13: J1.G13 R211.2
NetJ1_G27: J1.G27 R212.2
NetJ1_G28: J1.G28 R213.2
NetJ1_G30: J1.G30 R214.2
NetJ1_G31: J1.G31 R215.2
NetJ1_G33: J1.G33 R216.2
NetJ1_G34: J1.G34 R217.2
NetJ1_G36: J1.G36 R218.2
NetJ1_G37: J1.G37 R219.2
NetJ1_H25: J1.H25 R221.2
NetJ1_H26: J1.H26 R222.2
NetJ1_H28: J1.H28 R223.2
NetJ1_H29: J1.H29 R224.2
NetJ1_H31: J1.H31 R225.2
NetJ1_H32: J1.H32 R226.2
NetJ1_H34: J1.H34 R227.2
NetJ1_H37: J1.H37 R228.2

Not connected (* = marked no-connect by the designer): J1 F4 F5 F7 F8 F10 F11 F13 F14 F16 F17 F19 F20 F22 F23 F25 F26 F28 F29 F31 F32 F34 F35 F37 F38 G2 G3 G15 G16 G18 G19 G21 G22 G24 G25 H1 H4 H5 H7 H8 H10 H11 H13 H14 H16 H17 H19 H20 H22 H23 H35 H38 J2 J3 J6 J7 J9 J10 J12 J13 J15 J16 J18 J19 J21 J22 J24 J25 J27 J28 J30 J31 J33 J34 J36 J37 J39 K1 K4 K5 K7 K8 K10 K11 K13 K14 K16 K17 K19 K20 K22 K23 K25 K27 K28 K29 K31 K32 K34 K35 K37 K38 K40

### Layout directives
net class Power; net class FMCPwr: VADJ

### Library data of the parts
J1 = ASP-184330-01: as J1 on sheet FMC+ Sections A-E
R210-R219 R221-R228 = RSMD020101699: as R198-R209 on sheet FMC+ Sections A-E
R220 = RSMD040200375: RES SMD 100 OHM 1% 1/10W 0402; Manufacturer: Panasonic Electronic Components; CompType: Resistor SMD; Power (Watts): 0.1W, 1/10W; Temperature Coefficient: ±100ppm/°C; SizeX_mm: 1; SizeY_mm: 0.5; SizeZ_mm: 0.4

## Sheet FMC+ Sections Y, Z, L, M.SchDoc: FMC+ Section Rows L, M, Y & Z
size 431 x 279 mm; Date: Not shown in title block; ApprovedBy: Not shown in title block; CheckedBy: Not shown in title block; Author: Not shown in title block; CompanyName: Not shown in title block; Engineer: Not shown in title block; Organization: Not shown in title block; Address1: Not shown in title block; Address2: Not shown in title block; Address3: Not shown in title block; Address4: Not shown in title block; DocumentNumber: 1; Revision: Use project parameter SCH_Rev; SheetNumber: 19; SheetTotal: 21; PageSetup: Record=PageOptions¦CenterHorizontal=True¦CenterVertical=True¦PrintScale=1.00¦XCorrection=1.00¦YCorrection=1.00¦PrintKind=0¦BorderSize=5000000¦LeftOffset=0¦BottomOffset=0¦Orientation=2¦PaperLength=1000¦PaperWidth=1000¦Scale=100¦PaperSource=15¦PrintQuality=600¦MediaType=1¦DitherType=10¦PaperKind=Letter¦PrintScaleMode=1
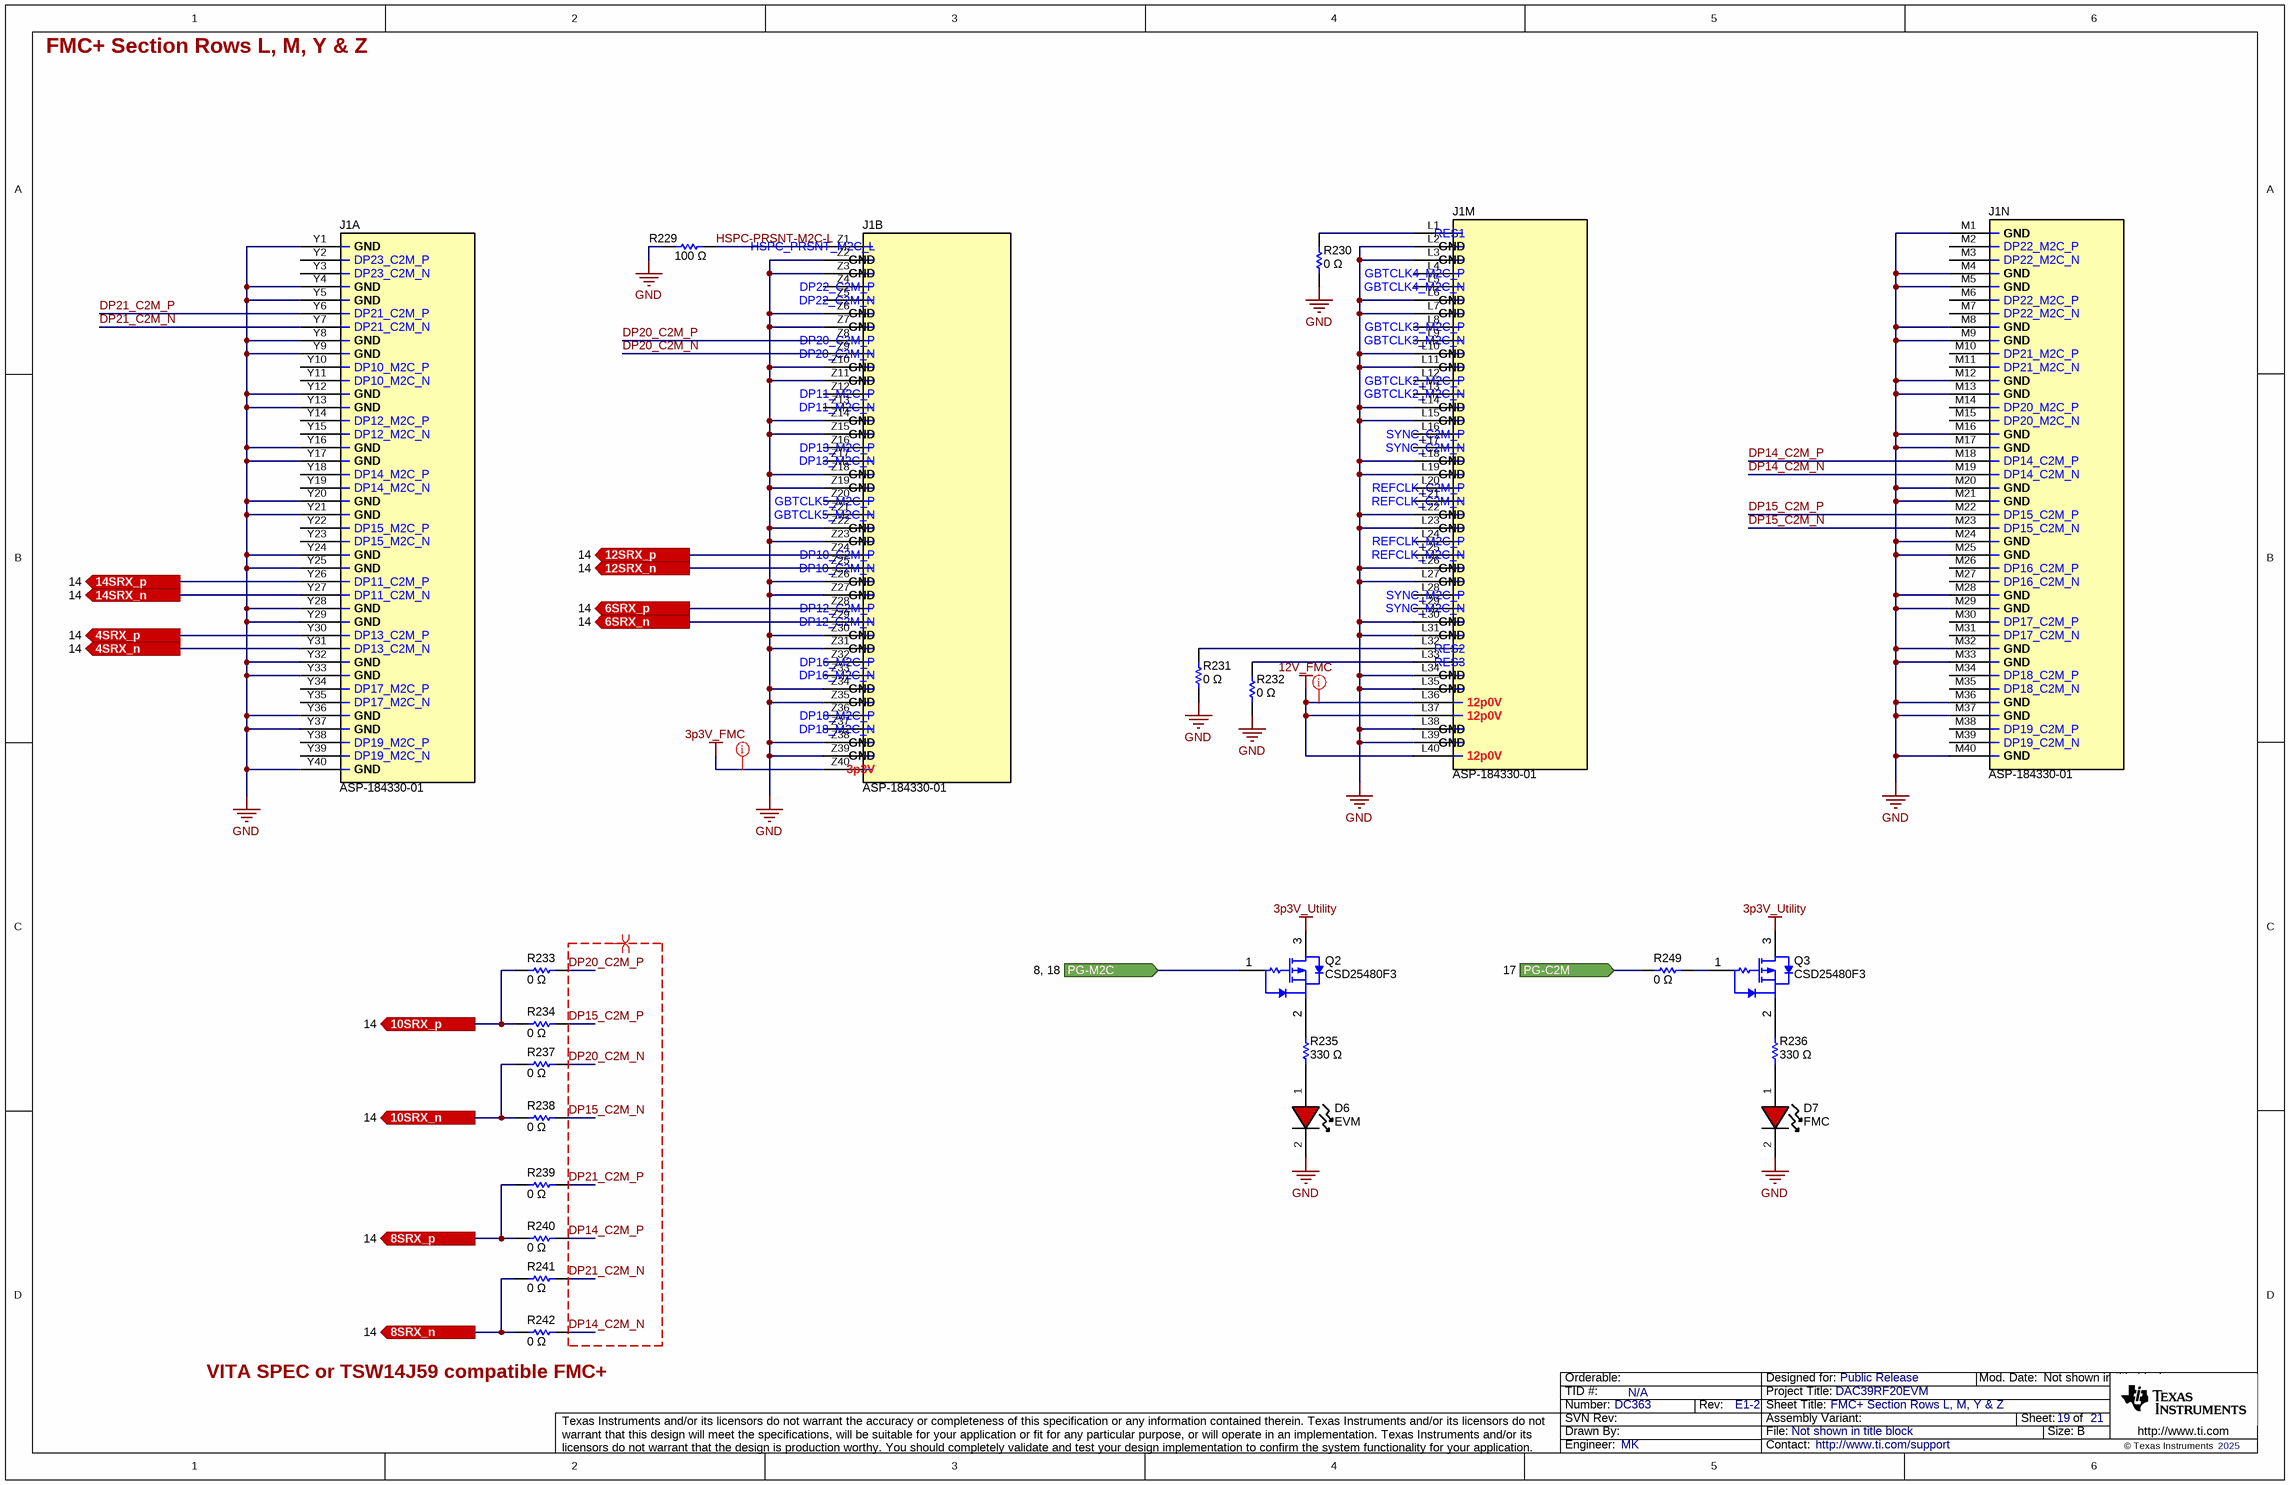
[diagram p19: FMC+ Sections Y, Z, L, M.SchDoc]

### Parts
D6  Text1: EVM  [LED_LTST-C190-Red]  (hidden comment: LTST-C190KRKT)
D7  Text1: FMC  [LED_LTST-C190-Red]  (hidden comment: LTST-C190KRKT)
J1  ASP-184330-01  [Samtec_ASP-184330-01]  (parts A,B,M,N of 14)
Q2  CSD25480F3  [YJM0003A]
Q3  CSD25480F3  [YJM0003A]
R229  value 100 Ω  [0402L]  (hidden comment: ERJ-2RKF1000X)
R230  value 0 Ω  [0201]  (hidden comment: ERJ-1GN0R00C)
R231  value 0 Ω  [0201]  (hidden comment: ERJ-1GN0R00C)
R232  value 0 Ω  [0201]  (hidden comment: ERJ-1GN0R00C)
R233  value 0 Ω  [0201]  (hidden comment: ERJ-1GN0R00C)
R234  value 0 Ω  [0201]  (hidden comment: ERJ-1GN0R00C)
R235  value 330 Ω  [0603L]  (hidden comment: ERJ-3GEYJ331V)
R236  value 330 Ω  [0603L]  (hidden comment: ERJ-3GEYJ331V)
R237  value 0 Ω  [0201]  (hidden comment: ERJ-1GN0R00C)
R238  value 0 Ω  [0201]  (hidden comment: ERJ-1GN0R00C)
R239  value 0 Ω  [0201]  (hidden comment: ERJ-1GN0R00C)
R240  value 0 Ω  [0201]  (hidden comment: ERJ-1GN0R00C)
R241  value 0 Ω  [0201]  (hidden comment: ERJ-1GN0R00C)
R242  value 0 Ω  [0201]  (hidden comment: ERJ-1GN0R00C)
R249  value 0 Ω  [0201]  (hidden comment: ERJ-1GN0R00C)

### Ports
4SRX_n (out, see 14), 4SRX_p (out, see 14), 6SRX_n (out, see 14), 6SRX_p (out, see 14), 8SRX_n (out, see 14), 8SRX_p (out, see 14), 10SRX_n (out, see 14), 10SRX_p (out, see 14), 12SRX_n (out, see 14), 12SRX_p (out, see 14), 14SRX_n (out, see 14), 14SRX_p (out, see 14), PG-C2M (in, see 17), PG-M2C (in, see 8, 18)

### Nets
3p3V_FMC: J1.Z40
3p3V_Utility: Q2.3(D) Q3.3(D)
12V_FMC: J1.L36 J1.L37 J1.L40
GND: D6.2(K) D7.2(K) J1.L2 J1.L3 J1.L6 J1.L7 J1.L10 J1.L11 J1.L14 J1.L15 J1.L18 J1.L19 J1.L22 J1.L23 J1.L26 J1.L27 J1.L30 J1.L31 J1.L34 J1.L35 J1.L38 J1.L39 J1.M1 J1.M4 J1.M5 J1.M8 J1.M9 J1.M12 J1.M13 J1.M16 J1.M17 J1.M20 J1.M21 J1.M24 J1.M25 J1.M28 J1.M29 J1.M32 J1.M33 J1.M36 J1.M37 J1.M40 J1.Y1 J1.Y4 J1.Y5 J1.Y8 J1.Y9 J1.Y12 J1.Y13 J1.Y16 J1.Y17 J1.Y20 J1.Y21 J1.Y24 J1.Y25 J1.Y28 J1.Y29 J1.Y32 J1.Y33 J1.Y36 J1.Y37 J1.Y40 J1.Z2 J1.Z3 J1.Z6 J1.Z7 J1.Z10 J1.Z11 J1.Z14 J1.Z15 J1.Z18 J1.Z19 J1.Z22 J1.Z23 J1.Z26 J1.Z27 J1.Z30 J1.Z31 J1.Z34 J1.Z35 J1.Z38 J1.Z39 R229.1 R230.1 R231.1 R232.1
4SRX_n: J1.Y31 ; port 4SRX_n
4SRX_p: J1.Y30 ; port 4SRX_p
6SRX_n: J1.Z29 ; port 6SRX_n
6SRX_p: J1.Z28 ; port 6SRX_p
8SRX_n: R241.2 R242.2 ; port 8SRX_n
8SRX_p: R239.2 R240.2 ; port 8SRX_p
10SRX_n: R237.2 R238.2 ; port 10SRX_n
10SRX_p: R233.2 R234.2 ; port 10SRX_p
12SRX_n: J1.Z25 ; port 12SRX_n
12SRX_p: J1.Z24 ; port 12SRX_p
14SRX_n: J1.Y27 ; port 14SRX_n
14SRX_p: J1.Y26 ; port 14SRX_p
DP14_C2M_N: J1.M19 R242.1
DP14_C2M_P: J1.M18 R240.1
DP15_C2M_N: J1.M23 R238.1
DP15_C2M_P: J1.M22 R234.1
DP20_C2M_N: J1.Z9 R237.1
DP20_C2M_P: J1.Z8 R233.1
DP21_C2M_N: J1.Y7 R241.1
DP21_C2M_P: J1.Y6 R239.1
HSPC-PRSNT-M2C-L: J1.Z1 R229.2
PG-C2M: R249.2 ; port PG-C2M
PG-M2C: Q2.1(G) ; port PG-M2C
NetD6_1: D6.1(A) R235.1
NetD7_1: D7.1(A) R236.1
NetJ1_L1: J1.L1 R230.2
NetJ1_L32: J1.L32 R231.2
NetJ1_L33: J1.L33 R232.2
NetQ2_2: Q2.2(S) R235.2
NetQ3_1: Q3.1(G) R249.1
NetQ3_2: Q3.2(S) R236.2

Not connected (* = marked no-connect by the designer): J1 L4 L5 L8 L9 L12 L13 L16 L17 L20 L21 L24 L25 L28 L29 M2 M3 M6 M7 M10 M11 M14 M15 M26 M27 M30 M31 M34 M35 M38 M39 Y2 Y3 Y10 Y11 Y14 Y15 Y18 Y19 Y22 Y23 Y34 Y35 Y38 Y39 Z4 Z5 Z12 Z13 Z16 Z17 Z20 Z21 Z32 Z33 Z36 Z37

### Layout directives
net class Power; net class FMCPwr: 3p3V_FMC, 12V_FMC
differential pair: DP14_C2M_N, DP14_C2M_P, DP15_C2M_N, DP15_C2M_P, DP20_C2M_N, DP20_C2M_P, DP21_C2M_N, DP21_C2M_P

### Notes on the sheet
- (near R242) VITA SPEC or TSW14J59 compatible FMC+ connection

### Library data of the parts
D6 D7 = cmp00244: LED RED CLEAR CHIP SMD; Manufacturer: Lite-On Inc.; Current Rating (Amps): 20mA; Voltage - Forward (Vf) (Typ): 2V; SizeX_mm: 1.6; SizeY_mm: 0.8; SizeZ_mm: 0.9
J1 = ASP-184330-01: as J1 on sheet FMC+ Sections A-E
Q2 Q3 = CSD25480F3: MOSFET, P-CH, -20 V, -1.7 A, YJM0003A (PICOSTAR-3); Alternate Manufacturer: None; Manufacturer: Texas Instruments; SymbolCreator: a0411947; AEC Category: Q101; QgTyp_nC: 0.7; Vgs_V: -12V; Value2: 0.7 nC; Rdson45_ohm: 0.159; SizeY_mm: 0.6; SizeZ_mm: 0.35; SizeArea_mm2: 0.414; ChType: P; AEC Qualified: N; Value1: 0.15; ChMode: Enhancement; VdsMax_V: -20V; SizeX_mm: 0.69; Value: -20V; SizeAreaWB_mm2: 2.704; IdsMax_A: -1.7A
R229 = RSMD040200375: as R220 on sheet FMC+ Sections F-H, J, K
R230-R234 R237-R242 R249 = RSMD020101699: as R198-R209 on sheet FMC+ Sections A-E
R235 R236 = RSMD060311096: RES SMD 330 OHM 5% 1/10W 0603; Manufacturer: Panasonic Electronic Components; CompType: Resistor SMD; Power (Watts): 0.1W, 1/10W; Temperature Coefficient: ±200ppm/°C; SizeX_mm: 1.6; SizeY_mm: 0.8; SizeZ_mm: 0.55

## Sheet Hardware & Mechanicals.SchDoc: Hardware & Mechanicals
size 431 x 279 mm; Date: Not shown in title block; ApprovedBy: Not shown in title block; CheckedBy: Not shown in title block; Author: Not shown in title block; CompanyName: Not shown in title block; Engineer: Not shown in title block; Organization: Not shown in title block; Address1: Not shown in title block; Address2: Not shown in title block; Address3: Not shown in title block; Address4: Not shown in title block; DocumentNumber: 4; Revision: Use project parameter SCH_Rev; SheetNumber: 20; SheetTotal: 21; PageSetup: Record=PageOptions¦CenterHorizontal=True¦CenterVertical=True¦PrintScale=1.00¦XCorrection=1.00¦YCorrection=1.00¦PrintKind=0¦BorderSize=5000000¦LeftOffset=0¦BottomOffset=0¦Orientation=2¦PaperLength=1000¦PaperWidth=1000¦Scale=100¦PaperSource=15¦PrintQuality=600¦MediaType=1¦DitherType=10¦PaperKind=Letter¦PrintScaleMode=1
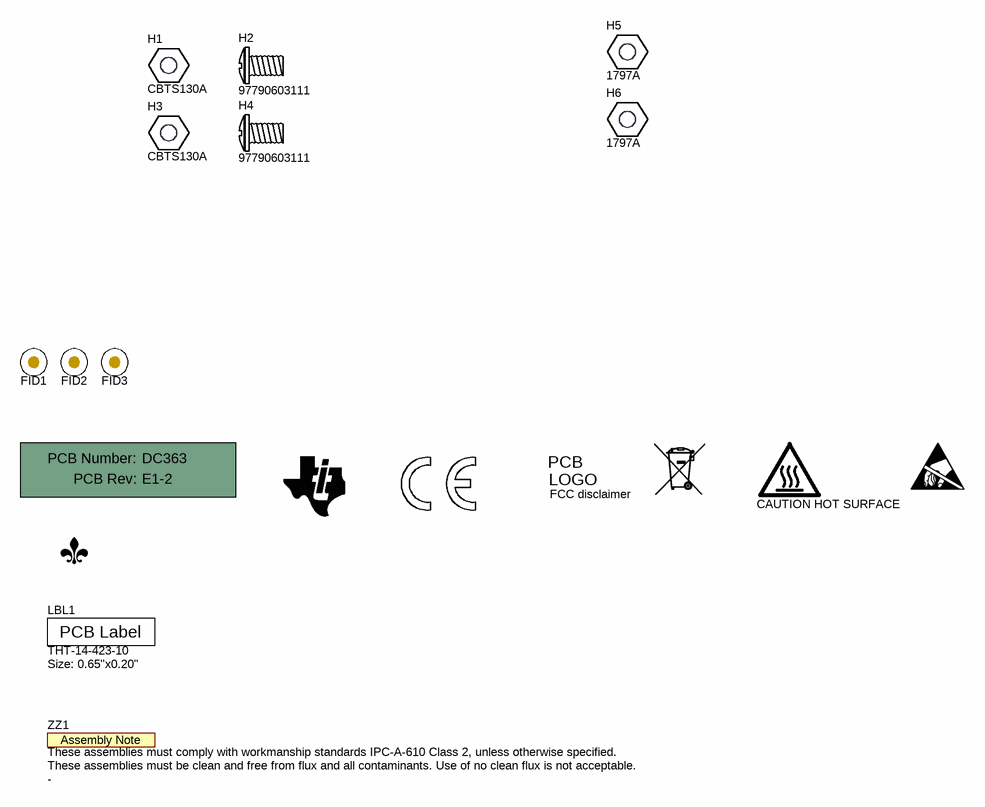
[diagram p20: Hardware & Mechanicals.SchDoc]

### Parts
!PCB1  (no value)  (mechanical)
FID1  Fiducial Mark  [Fiducial10-20]  (value not drawn)  (no BOM)
FID2  Fiducial Mark  [Fiducial10-20]  (value not drawn)  (no BOM)
FID3  Fiducial Mark  [Fiducial10-20]  (value not drawn)  (no BOM)
H1  CBTS130A  [cbts130a]
H2  97790603111  [97790603111]  (mechanical)
H3  CBTS130A  [cbts130a]
H4  97790603111  [97790603111]  (mechanical)
H5  1797A  [Keystone_1797B]
H6  1797A  [Keystone_1797B]
LBL1  THT-14-423-10  Text1: Size: 0.65"x0.20"  [Label_650x200]
LOGO1  CAUTION HOT SURFACE  [IEC_HotSurface_Small]  (no BOM)
Logo2  FCC disclaimer  [FCC_disclaimer]  (no BOM)
Logo3  ESD Overlay  [ESD_Overlay_Small]  (value not drawn)  (no BOM)
Logo4  WEEE  [WEEE_Minimum]  (value not drawn)  (no BOM)
LOGO5  CE Mark  [CE_Mark_5mm]  (value not drawn)  (no BOM)
Logo6  Texas Instruments  [TI_Stacked_Overlay_Small_Vertical]  (value not drawn)  (no BOM)
Logo7  FDL Logo  [FDL_Small]  (value not drawn)  (no BOM)
Logo8  Texas Instruments  [TI_Symbol_Overlay_Medium]  (value not drawn)  (no BOM)
ZZ1  Text3: These assemblies must comply with workmanship standards IPC-A-610 Class 2, unless otherwise specified.  Text2: These assemblies must be clean and free from flux and all contaminants. Use of no clean flux is not acceptable.  [AssemblyNote]  (hidden comment: These assemblies are ESD sensitive, ESD precautions shall be observed.)  (no BOM)

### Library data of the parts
!PCB1 = cmp00109: Printed Circuit Board; CompType: PCB
FID1-FID3 = cmp00099: Fiducial; SymbolCreator: a0412235
H1 H3 = CBTS130A: Hex Standoff Threaded M3 Nylon 1.260" (32.00mm) Natural; Manufacturer: Essentra Components; UniqueID: CBTS010A
H2 H4 = 97790603111: M3 Pan Head Machine Screw Phillips Drive Nylon; Manufacturer: Murth Elektronik
H5 H6 = cmp00098: Hex Standoff Threaded #2-56 Aluminum 0.188" (4.78mm) 3/16"; Manufacturer: RAF Electronic Hardware; Pitch (mm): 2-56
LBL1 = cmp00106: Thermal Transfer Printable Labels, 0.650" W x 0.200" H - 10,000 per roll; Manufacturer: Brady; CompType: Label
LOGO1 = cmp00100: IEC 61010-1 Hot Surface Warning; PartNumber: IEC_HotSurface; CompType: Logo
Logo2 = cmp00102: FCC_disclaimer; CompType: Logo
Logo3 = cmp00317: PartNumber: ESD Logo; CompType: Logo
Logo4 = cmp00101: CompType: Logo
LOGO5 = cmp00103: CE_Mark; CompType: Logo
Logo6 Logo8 = cmp00104: Texas Instrument Corporate Signature; PartNumber: TI Bug; CompType: Logo
Logo7 = cmp00105: FDL
ZZ1 = cmp00108: Assembly Notes

## Sheet Revision History.SchDoc: Rev History & Variants
size 431 x 279 mm; Date: Not shown in title block; ApprovedBy: Not shown in title block; CheckedBy: Not shown in title block; Author: Not shown in title block; CompanyName: Not shown in title block; Engineer: Not shown in title block; Organization: Not shown in title block; Address1: Not shown in title block; Address2: Not shown in title block; Address3: Not shown in title block; Address4: Not shown in title block; DocumentNumber: 5; Revision: Use project parameter SCH_Rev; SheetNumber: 5; SheetTotal: 5; PageSetup: Record=PageOptions¦CenterHorizontal=True¦CenterVertical=True¦PrintScale=1.00¦XCorrection=1.00¦YCorrection=1.00¦PrintKind=0¦BorderSize=5000000¦LeftOffset=0¦BottomOffset=0¦Orientation=2¦PaperLength=1000¦PaperWidth=1000¦Scale=100¦PaperSource=15¦PrintQuality=600¦MediaType=1¦DitherType=10¦PaperKind=Letter¦PrintScaleMode=1
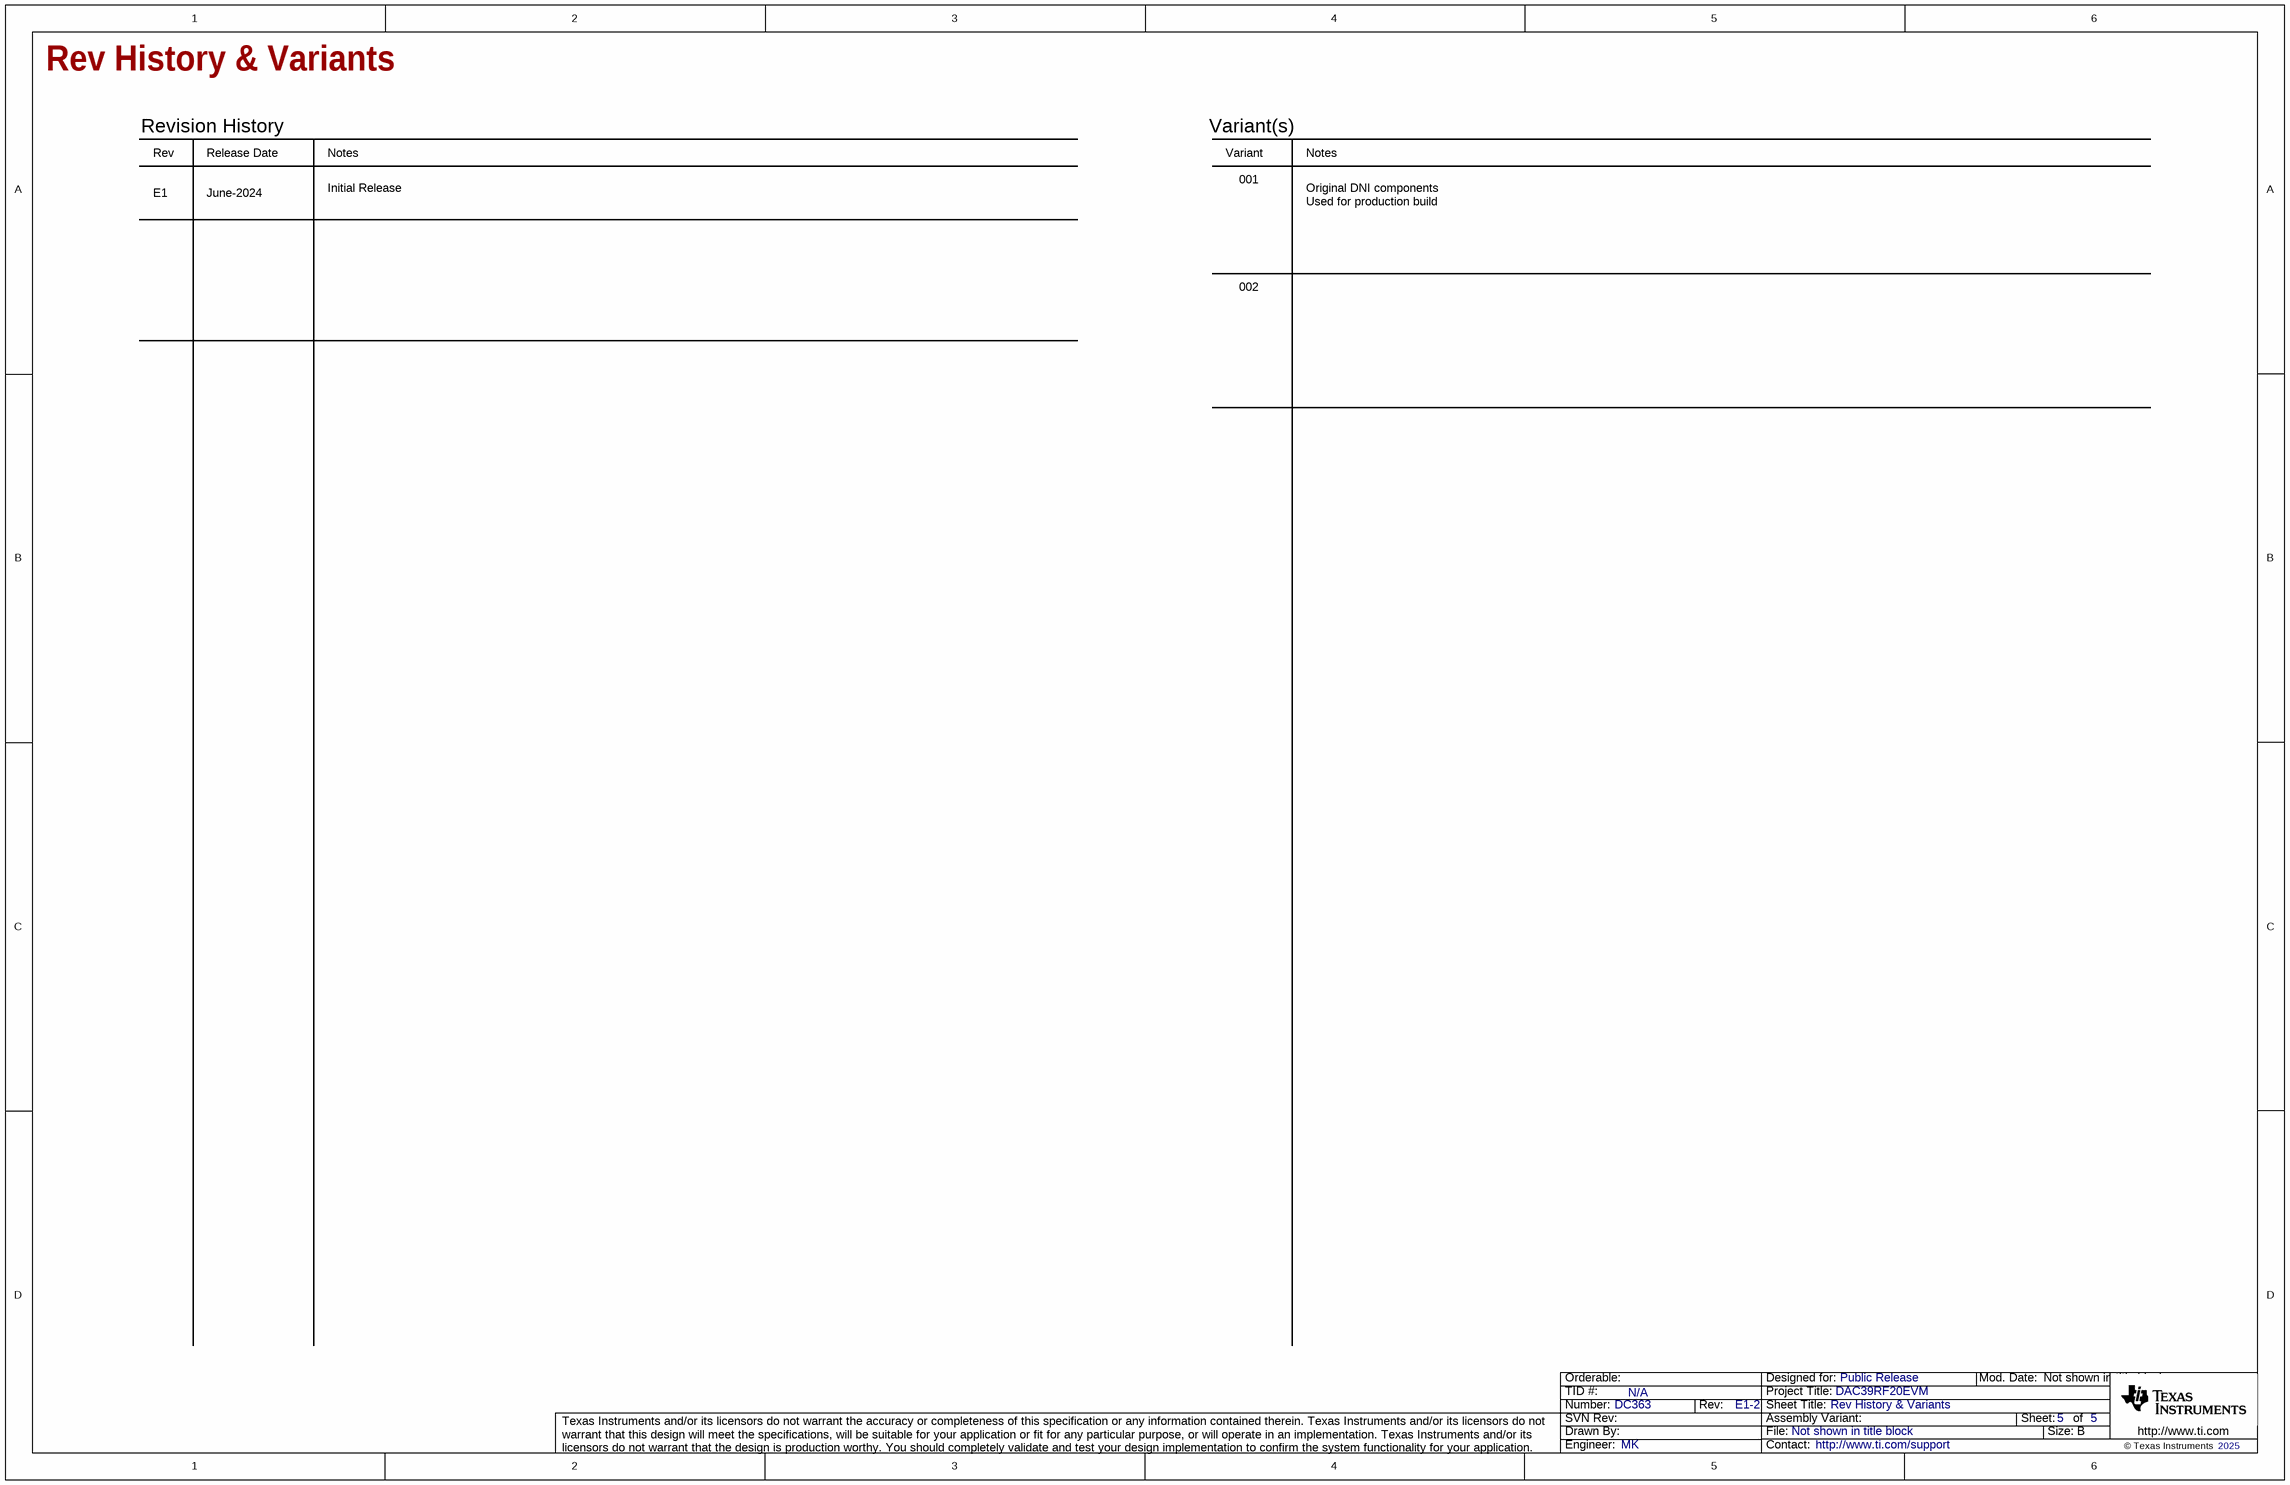
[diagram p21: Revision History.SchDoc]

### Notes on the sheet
- Rev
- Release Date
- Revision History
- Notes
- Variant
- Variant(s)
- E1
- June-2024
- Initial Release
- 001
- 002
- Original DNI components
  Used for production build

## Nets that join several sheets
2p3V: Power DC-DC Analog (5 pins), Power LDO 1p8V Analog (5 pins), Power LDO 0p8V Analog (10 pins)
3p3V_Clock: Power LMK (FC1.3), LMK LVL Shift and Mux (R138.1), Clocking LMK04828 (24 pins)
3p3V_FMC: FMC+ Sections A-E (7 pins), FMC+ Sections Y, Z, L, M (J1.Z40)
3p3V_Utility: 12V Input, Efuse and 3p3V Utility (6 pins), Power Sense ADC (19 pins), Power DC-DC Digital (5 pins), Power DC-DC Analog (R33.2 R38.2), Power LDO 1p8V Analog (C48.2 R44.2 U15.5), Power LDO N1p8V Analog (12 pins), Power LDO 0p8V Analog (14 pins), Power LMK (C104.2 R90.2 U34.5), USB Control FTDI (21 pins), I2C & DAC LVL Shift and MUX (15 pins), LMK LVL Shift and Mux (13 pins), DUT IO (C217.2 R176.2 R177.2 U55.1), FMC+ Sections A-E (D5.1), FMC+ Sections Y, Z, L, M (Q2.3 Q3.3)
3p8V: Power DC-DC Analog (5 pins), Power LDO N1p8V Analog (6 pins), Power LMK (5 pins)
12V: 12V Input, Efuse and 3p3V Utility (14 pins), Power DC-DC Digital (9 pins), Power DC-DC Analog (8 pins)
12V_FMC: 12V Input, Efuse and 3p3V Utility (SW1.3), FMC+ Sections A-E (J1.C35 J1.C37), FMC+ Sections Y, Z, L, M (J1.L36 J1.L37 J1.L40)
DVDD: Power DC-DC Digital (PP11.1 R22.1 R23.3 R24.2), DUT Power (85 pins)
GND: 12V Input, Efuse and 3p3V Utility (26 pins), Power Sense ADC (22 pins), Power DC-DC Digital (35 pins), Power DC-DC Analog (48 pins), Power LDO 1p8V Analog (22 pins), Power LDO N1p8V Analog (32 pins), Power LDO 0p8V Analog (40 pins), Power LMK (15 pins), USB Control FTDI (49 pins), I2C & DAC LVL Shift and MUX (20 pins), LMK LVL Shift and Mux (32 pins), Clocking LMK04828 (34 pins), DUT IO (21 pins), DUT Outputs (28 pins), DUT Power (217 pins), FMC+ Sections A-E (99 pins), FMC+ Sections F-H, J, K (72 pins), FMC+ Sections Y, Z, L, M (86 pins)
VADJ: USB Control FTDI (6 pins), I2C & DAC LVL Shift and MUX (SW3.2), FMC+ Sections A-E (J1.E39), FMC+ Sections F-H, J, K (J1.F40 J1.G39 J1.H40)
VDD_FPGA: I2C & DAC LVL Shift and MUX (8 pins), LMK LVL Shift and Mux (13 pins)
VDDA18A: Power LDO 1p8V Analog (C63.3 PP21.1), DUT Outputs (T2.3 T4.3), DUT Power (C289.1 C290.1 U1.G16 U1.G17)
VDDA18B: Power LDO 1p8V Analog (C64.3 PP22.1), DUT Outputs (T6.3 T8.3), DUT Power (C287.1 C288.1 U1.L16 U1.L17)
VDDCLK08: Power LDO 0p8V Analog (7 pins), DUT Power (18 pins)
VDDCLK18: Power LDO 1p8V Analog (C62.3 PP20.1), DUT Power (C291.1 C292.1 U1.L14 U1.M14)
VDDCP18: Power LDO 1p8V Analog (C61.3 PP19.1), DUT Power (C282.1 C283.1 U1.J13 U1.J14)
VDDIO: Power LDO 1p8V Analog (C59.3 PP17.1), I2C & DAC LVL Shift and MUX (5 pins), LMK LVL Shift and Mux (8 pins), DUT Power (C280.1 C281.1 U1.C9 U1.C10)
VDDLA: Power LDO 0p8V Analog (C83.3 PP26.1), DUT Power (C276.1 C277.1 U1.F11 U1.H11)
VDDLB: Power LDO 0p8V Analog (C89.3 PP27.1), DUT Power (C278.1 C279.1 U1.K11 U1.M11)
VDDR18: Power LDO 1p8V Analog (C51.3 PP15.1), DUT Power (C284.1 U1.N4 U1.P4)
VDDSP18: Power LDO 1p8V Analog (C60.3 PP18.1), DUT Power (C293.1 U1.J10)
VDDSYS18: Power LDO 1p8V Analog (C57.3 PP16.1), DUT Power (C285.1 C286.1 U1.F14 U1.G14)
VEEAM18: Power LDO N1p8V Analog (C69.3), DUT Power (12 pins)
VEEBM18: Power LDO N1p8V Analog (C77.3), DUT Power (12 pins)
0SRX_n: DUT IO (C179.2), FMC+ Sections A-E (J1.A39)
0SRX_p: DUT IO (C178.2), FMC+ Sections A-E (J1.A38)
1SRX_n: DUT IO (C181.2), FMC+ Sections A-E (J1.B37)
1SRX_p: DUT IO (C180.2), FMC+ Sections A-E (J1.B36)
2SRX_n: DUT IO (C187.2), FMC+ Sections A-E (J1.B33)
2SRX_p: DUT IO (C185.2), FMC+ Sections A-E (J1.B32)
3SRX_n: DUT IO (C189.2), FMC+ Sections A-E (J1.A35)
3SRX_p: DUT IO (C188.2), FMC+ Sections A-E (J1.A34)
4SRX_n: DUT IO (C193.2), FMC+ Sections Y, Z, L, M (J1.Y31)
4SRX_p: DUT IO (C191.2), FMC+ Sections Y, Z, L, M (J1.Y30)
5SRX_n: DUT IO (C195.2), FMC+ Sections A-E (J1.A31)
5SRX_p: DUT IO (C194.2), FMC+ Sections A-E (J1.A30)
6SRX_n: DUT IO (C198.2), FMC+ Sections Y, Z, L, M (J1.Z29)
6SRX_p: DUT IO (C196.2), FMC+ Sections Y, Z, L, M (J1.Z28)
7SRX_n: DUT IO (C200.2), FMC+ Sections A-E (J1.B29)
7SRX_p: DUT IO (C199.2), FMC+ Sections A-E (J1.B28)
8SRX_n: DUT IO (C202.2), FMC+ Sections Y, Z, L, M (R241.2 R242.2)
8SRX_p: DUT IO (C201.2), FMC+ Sections Y, Z, L, M (R239.2 R240.2)
9SRX_n: DUT IO (C204.2), FMC+ Sections A-E (J1.C3)
9SRX_p: DUT IO (C203.2), FMC+ Sections A-E (J1.C2)
10SRX_n: DUT IO (C206.2), FMC+ Sections Y, Z, L, M (R237.2 R238.2)
10SRX_p: DUT IO (C205.2), FMC+ Sections Y, Z, L, M (R233.2 R234.2)
11SRX_n: DUT IO (C208.2), FMC+ Sections A-E (J1.A23)
11SRX_p: DUT IO (C207.2), FMC+ Sections A-E (J1.A22)
12SRX_n: DUT IO (C210.2), FMC+ Sections Y, Z, L, M (J1.Z25)
12SRX_p: DUT IO (C209.2), FMC+ Sections Y, Z, L, M (J1.Z24)
13SRX_n: DUT IO (C212.2), FMC+ Sections A-E (J1.B25)
13SRX_p: DUT IO (C211.2), FMC+ Sections A-E (J1.B24)
14SRX_n: DUT IO (C214.2), FMC+ Sections Y, Z, L, M (J1.Y27)
14SRX_p: DUT IO (C213.2), FMC+ Sections Y, Z, L, M (J1.Y26)
15SRX_n: DUT IO (C216.2), FMC+ Sections A-E (J1.A27)
15SRX_p: DUT IO (C215.2), FMC+ Sections A-E (J1.A26)
CCLK_SHIFT: USB Control FTDI (U38.14), FMC+ Sections A-E (R199.1)
COMM_MUX_CTRL: I2C & DAC LVL Shift and MUX (SW2.1 U43.1 U43.5), LMK LVL Shift and Mux (U48.15 U52.15)
DAC_ALARM: I2C & DAC LVL Shift and MUX (U45.6), DUT IO (PP56.1 U1.E3)
DAC_ALARM_FMC: I2C & DAC LVL Shift and MUX (U45.3), FMC+ Sections F-H, J, K (R210.1)
DAC_~{CS}: LMK LVL Shift and Mux (PP45.1 R151.2 U52.10), DUT IO (U1.K3)
DAC_~{RESET}: I2C & DAC LVL Shift and MUX (R135.2), DUT IO (PP61.1 U1.E5)
DAC_~{RESET}_FMC: I2C & DAC LVL Shift and MUX (R134.2 U46.12), FMC+ Sections F-H, J, K (R214.1)
DAC_SCLK: LMK LVL Shift and Mux (PP42.1 R154.1 U52.2), DUT IO (U1.J1)
DAC_SDI: LMK LVL Shift and Mux (PP43.1 R155.1 U52.5), DUT IO (U1.J3)
DAC_SDO: LMK LVL Shift and Mux (PP44.1 R156.1 U52.7), DUT IO (U1.J2)
DAC_SYSREF_LMK_N: Clocking LMK04828 (C163.1), DUT IO (R173.2)
DAC_SYSREF_LMK_P: Clocking LMK04828 (C162.1), DUT IO (R171.2)
DAC_TXEN0: I2C & DAC LVL Shift and MUX (R137.2), DUT IO (PP63.1 U1.G3)
DAC_TXEN0_FMC: I2C & DAC LVL Shift and MUX (R132.2 U46.10), FMC+ Sections F-H, J, K (R212.1)
DAC_TXEN1: I2C & DAC LVL Shift and MUX (R136.2), DUT IO (PP64.1 U1.H3)
DAC_TXEN1_FMC: I2C & DAC LVL Shift and MUX (R133.2 U46.11), FMC+ Sections F-H, J, K (R213.1)
DACOUTA_n: DUT IO (U1.A13), DUT Outputs (R186.1 R187.1)
DACOUTA_p: DUT IO (U1.A11), DUT Outputs (R182.1 R183.1)
DACOUTB_n: DUT IO (U1.U13), DUT Outputs (R192.1 R193.1)
DACOUTB_p: DUT IO (U1.U11), DUT Outputs (R188.1 R189.1)
DIN_SHIFT: USB Control FTDI (U38.13), FMC+ Sections A-E (R201.1)
DONE_SHIFT: USB Control FTDI (U38.11), FMC+ Sections A-E (R202.1)
F2F_RST_SHIFT: USB Control FTDI (U42.7), FMC+ Sections F-H, J, K (R211.1)
F2F_SCLK_SHIFT: USB Control FTDI (U39.14), FMC+ Sections A-E (PP67.1 R203.1)
F2F_SDI_SHIFT: USB Control FTDI (U39.11), FMC+ Sections A-E (PP65.1 R204.1)
F2F_SDO_SHIFT: USB Control FTDI (U39.12), FMC+ Sections A-E (PP68.1 R206.1)
F2F_SEN_SHIFT: USB Control FTDI (U39.13), FMC+ Sections A-E (PP66.1 R205.1)
FMC_~{CS}_DAC: LMK LVL Shift and Mux (PP38.1 R139.2 U49.5), FMC+ Sections F-H, J, K (R227.1)
FMC_~{CS}_LMK: LMK LVL Shift and Mux (PP36.1 R140.2 U47.5), FMC+ Sections F-H, J, K (R221.1)
FMC_I2C_SCL: I2C & DAC LVL Shift and MUX (U43.7), FMC+ Sections A-E (R208.1)
FMC_I2C_SDA: I2C & DAC LVL Shift and MUX (U43.9), FMC+ Sections A-E (R209.1)
FMC_SCLK: LMK LVL Shift and Mux (PP39.1 U47.3 U49.3), FMC+ Sections F-H, J, K (R215.1)
FMC_SDI: LMK LVL Shift and Mux (PP37.1 U47.4 U49.4), FMC+ Sections F-H, J, K (R216.1)
FMC_SDO: LMK LVL Shift and Mux (PP41.1 U49.6), FMC+ Sections F-H, J, K (R217.1)
FMC_TRIG0: DUT IO (R244.1), FMC+ Sections F-H, J, K (R223.1)
FMC_TRIG1: DUT IO (R245.1), FMC+ Sections F-H, J, K (R224.1)
FMC_TRIG2: DUT IO (R246.1), FMC+ Sections F-H, J, K (R218.1)
FMC_TRIG3: DUT IO (R247.1), FMC+ Sections F-H, J, K (R219.1)
FMC_TRIG4: DUT IO (R248.1), FMC+ Sections F-H, J, K (R228.1)
FMC_TRIGCLK: DUT IO (R243.1), FMC+ Sections F-H, J, K (R222.1)
FPGA_CORECLK_n: Clocking LMK04828 (C167.1), FMC+ Sections F-H, J, K (J1.G7)
FPGA_CORECLK_p: Clocking LMK04828 (C166.1), FMC+ Sections F-H, J, K (J1.G6)
FPGA_SYSREF_n: Clocking LMK04828 (C175.1), FMC+ Sections F-H, J, K (J1.G10)
FPGA_SYSREF_p: Clocking LMK04828 (C174.1), FMC+ Sections F-H, J, K (J1.G9)
FTDI_I2C_SCL: USB Control FTDI (R98.2 U36.3), I2C & DAC LVL Shift and MUX (U43.4)
GBTCLK0_FMC_n: Clocking LMK04828 (C173.1), FMC+ Sections A-E (J1.D5)
GBTCLK0_FMC_p: Clocking LMK04828 (C172.1), FMC+ Sections A-E (J1.D4)
GBTCLK1_FMC_n: Clocking LMK04828 (C169.1), FMC+ Sections A-E (J1.B21)
GBTCLK1_FMC_p: Clocking LMK04828 (C168.1), FMC+ Sections A-E (J1.B20)
ISENSE-DVDD: Power Sense ADC (U5.7), Power DC-DC Digital (U9.4)
ISENSE-VDD18: Power Sense ADC (U5.5), Power LDO 1p8V Analog (U15.4)
ISENSE-VDDCLK08: Power Sense ADC (U5.8), Power LDO 0p8V Analog (U30.4)
ISENSE-VDDLx: Power Sense ADC (U5.9), Power LDO 0p8V Analog (U26.4)
ISENSE-VEEAM18: Power Sense ADC (U5.10), Power LDO N1p8V Analog (U20.1)
ISENSE-VEEBM18: Power Sense ADC (U5.3), Power LDO N1p8V Analog (U25.1)
ISENSE_CLOCKING: Power Sense ADC (U5.4), Power LMK (U34.4)
LMK_~{CS}: LMK LVL Shift and Mux (PP35.1 R138.2 U48.10), Clocking LMK04828 (U54.18)
LMK_SCLK: LMK LVL Shift and Mux (PP32.1 R142.1 U48.2), Clocking LMK04828 (U54.19)
LMK_SDI: LMK LVL Shift and Mux (PP33.1 R143.1 U48.5), Clocking LMK04828 (U54.20)
LMK_SDO: LMK LVL Shift and Mux (PP34.1 R144.1 U48.7), Clocking LMK04828 (U54.58)
PG-1p8V: Power LDO 1p8V Analog (R44.1 U16.4), Power LDO N1p8V Analog (U18.8 U23.8)
PG-2p3V: Power DC-DC Analog (R33.1 U13.19), Power LDO 1p8V Analog (R45.1 U16.3)
PG-C2M: FMC+ Sections A-E (J1.D1), FMC+ Sections Y, Z, L, M (R249.2)
PG-M2C: Power LDO 0p8V Analog (R68.1 R79.1 U27.4 U32.4), FMC+ Sections F-H, J, K (J1.F1), FMC+ Sections Y, Z, L, M (Q2.1)
PG-n1p8V: Power LDO N1p8V Analog (U21.4), Power LDO 0p8V Analog (R69.1 R82.1 U27.3 U32.3)
PROG_B_SHIFT: USB Control FTDI (U38.12), FMC+ Sections A-E (R200.1)
~{SYNC}_DAC: I2C & DAC LVL Shift and MUX (R250.2 R253.2), DUT IO (PP59.1 U1.E4)
~{SYNC}_FMC: I2C & DAC LVL Shift and MUX (R251.2 R252.2), FMC+ Sections F-H, J, K (R225.1 R226.1)
SCL-ADC: Power Sense ADC (U7.14 U8.12), I2C & DAC LVL Shift and MUX (R126.1 U44.8)
SCL-DVDD: Power DC-DC Digital (U11.3 U12.3), I2C & DAC LVL Shift and MUX (R120.1 U44.2)
SCL-VDDCLK: Power LDO 0p8V Analog (U31.3 U33.3), I2C & DAC LVL Shift and MUX (R124.1 U44.6)
SCL-VDDL: Power LDO 0p8V Analog (U28.3 U29.3), I2C & DAC LVL Shift and MUX (R122.1 U44.4)
SCL_I2C: I2C & DAC LVL Shift and MUX (PP31.1 U43.6 U44.19), DUT IO (U55.8), FMC+ Sections A-E (U60.7)
SDA-ADC: Power Sense ADC (U7.13 U8.13), I2C & DAC LVL Shift and MUX (R125.1 U44.7)
SDA-DVDD: Power DC-DC Digital (U11.4 U12.4), I2C & DAC LVL Shift and MUX (R119.1 U44.1)
SDA-VDDCLK: Power LDO 0p8V Analog (U31.4 U33.4), I2C & DAC LVL Shift and MUX (R123.1 U44.5)
SDA-VDDL: Power LDO 0p8V Analog (U28.4 U29.4), I2C & DAC LVL Shift and MUX (R121.1 U44.3)
SDA_I2C: I2C & DAC LVL Shift and MUX (PP30.1 U43.10 U44.20), DUT IO (U55.7), FMC+ Sections A-E (U60.9)
USB_~{CS}_DAC_3p3: USB Control FTDI (U37.19), LMK LVL Shift and Mux (R152.2 U53.6)
USB_~{CS}_LMK_3p3: USB Control FTDI (U37.54), LMK LVL Shift and Mux (U48.11)
USB_I2C_SDAr: USB Control FTDI (R101.2 R103.2 U37.28), I2C & DAC LVL Shift and MUX (U43.2)
USB_SCLK_DAC_3p3: USB Control FTDI (R99.2), LMK LVL Shift and Mux (U53.3)
USB_SCLK_LMK_3p3: USB Control FTDI (R107.2), LMK LVL Shift and Mux (U48.1)
USB_SDI_DAC_3p3: USB Control FTDI (U37.17), LMK LVL Shift and Mux (U53.4)
USB_SDI_LMK_3p3: USB Control FTDI (U37.52), LMK LVL Shift and Mux (U48.4)
USB_SDO_DAC_3p3: USB Control FTDI (U37.18), LMK LVL Shift and Mux (U53.5)
USB_SDO_LMK_3p3: USB Control FTDI (U37.53), LMK LVL Shift and Mux (U48.8)
VSENSE-DVDD: Power Sense ADC (U6.7), Power DC-DC Digital (R22.2)
VSENSE-VDD18: Power Sense ADC (U6.5), Power LDO 1p8V Analog (R43.2)
VSENSE-VDDCLK08: Power Sense ADC (U6.8), Power LDO 0p8V Analog (R78.2)
VSENSE-VDDLx: Power Sense ADC (U6.9), Power LDO 0p8V Analog (R67.2)
VSENSE-VEEAM18: Power Sense ADC (U6.10), Power LDO N1p8V Analog (R58.2)
VSENSE-VEEBM18: Power Sense ADC (U6.3), Power LDO N1p8V Analog (R66.2)
VSENSE_CLOCKING: Power Sense ADC (U6.4), Power LMK (R89.2)

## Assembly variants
001: not fitted C182 C183 C192 C222 C223 C225 C230 C231 C233 H5 H6 J8 J10 J11 J12 R7 R45 R67 R69 R82 R135 R142 R143 R144 R148 R154 R155 R156 R158 R172 R174 R182 R184 R187 R188 R190 R193 R205 R222 R234 R238 R240 R242 R249 R250 R251 TP1 TP2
